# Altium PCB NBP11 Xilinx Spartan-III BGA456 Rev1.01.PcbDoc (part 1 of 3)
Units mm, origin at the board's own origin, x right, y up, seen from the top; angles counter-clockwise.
Board outline 69 x 80.99 mm, 6 copper layers (Top Layer, MidLayer1, InternalPlane1, InternalPlane2, MidLayer2, Bottom Layer); 105 components, 277 nets, 967 pads, 559 vias.
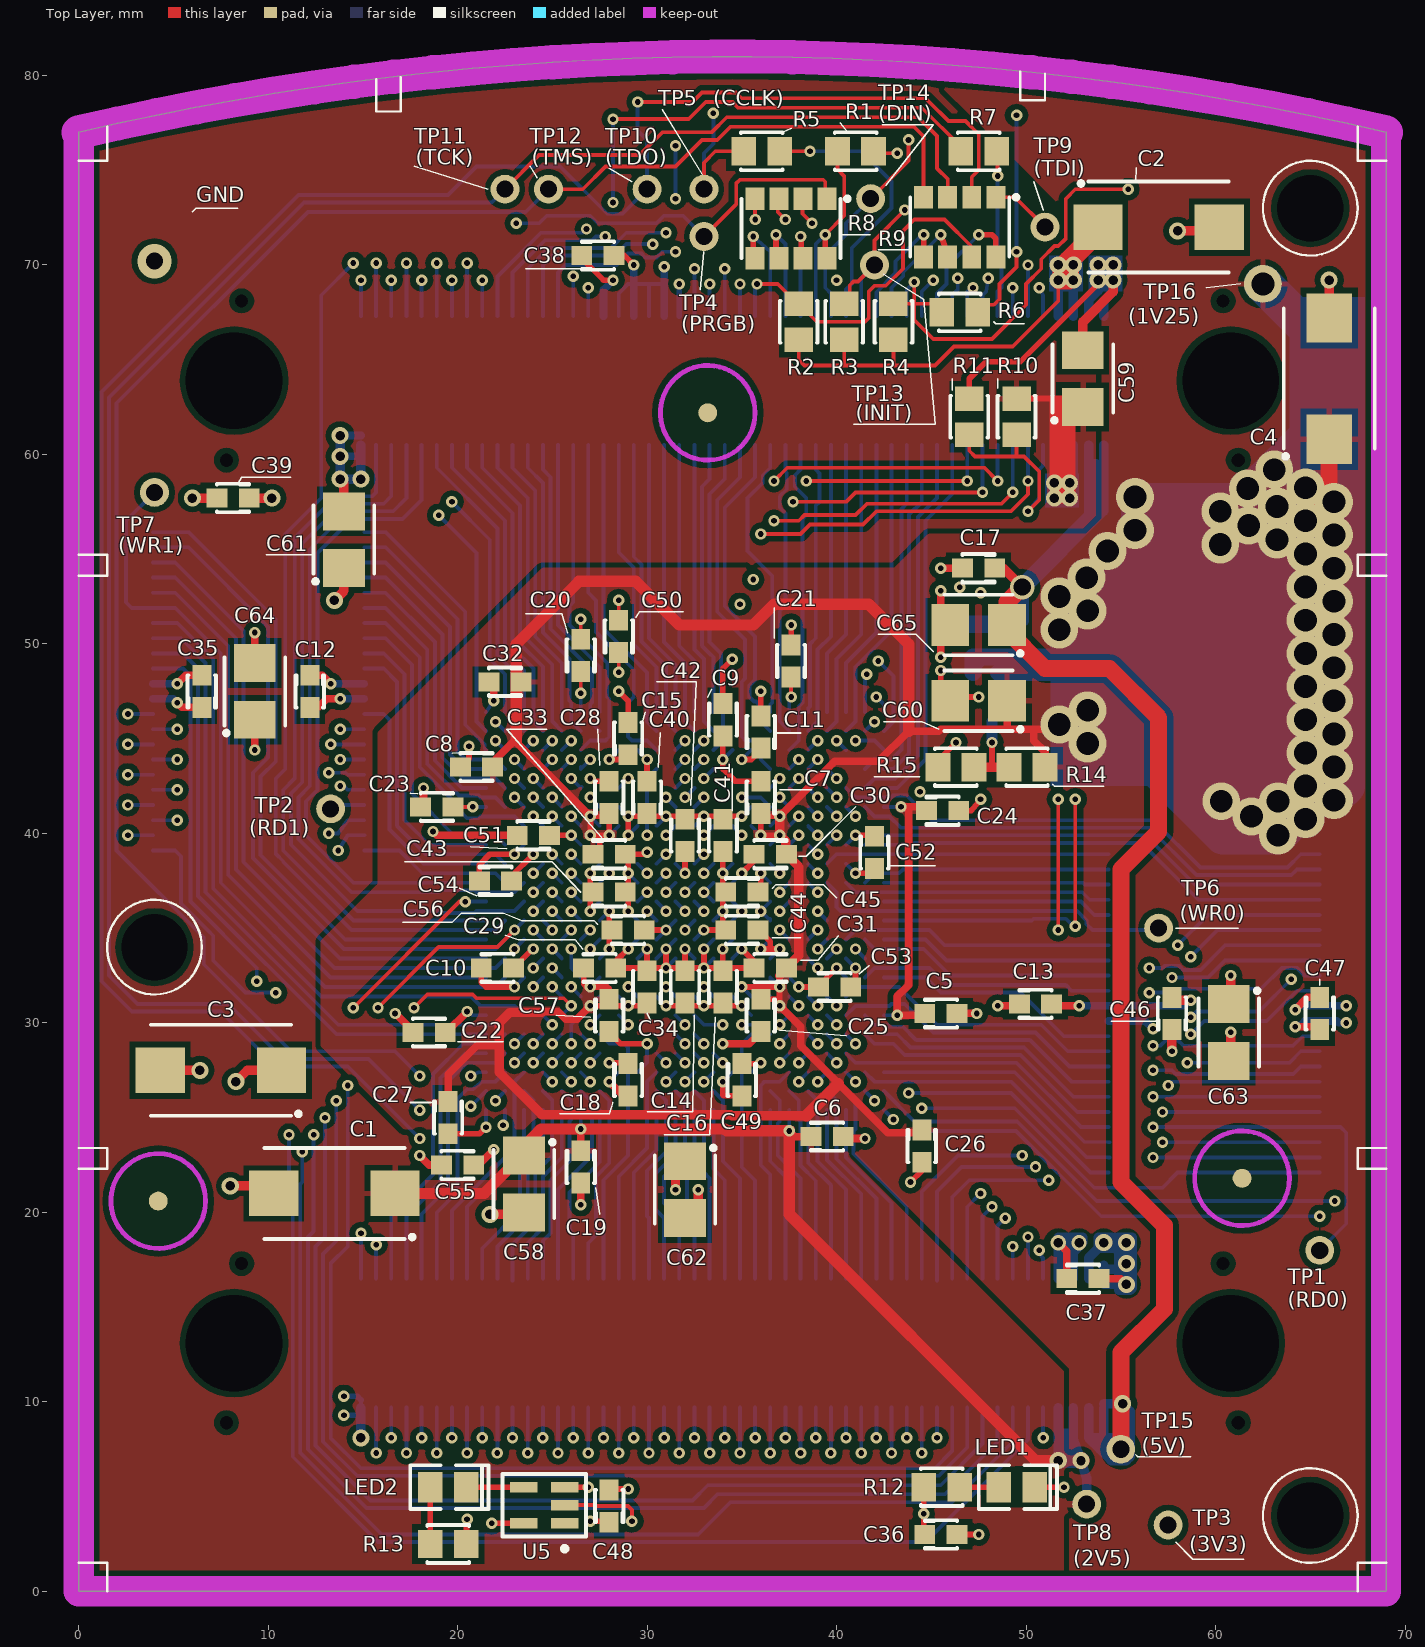
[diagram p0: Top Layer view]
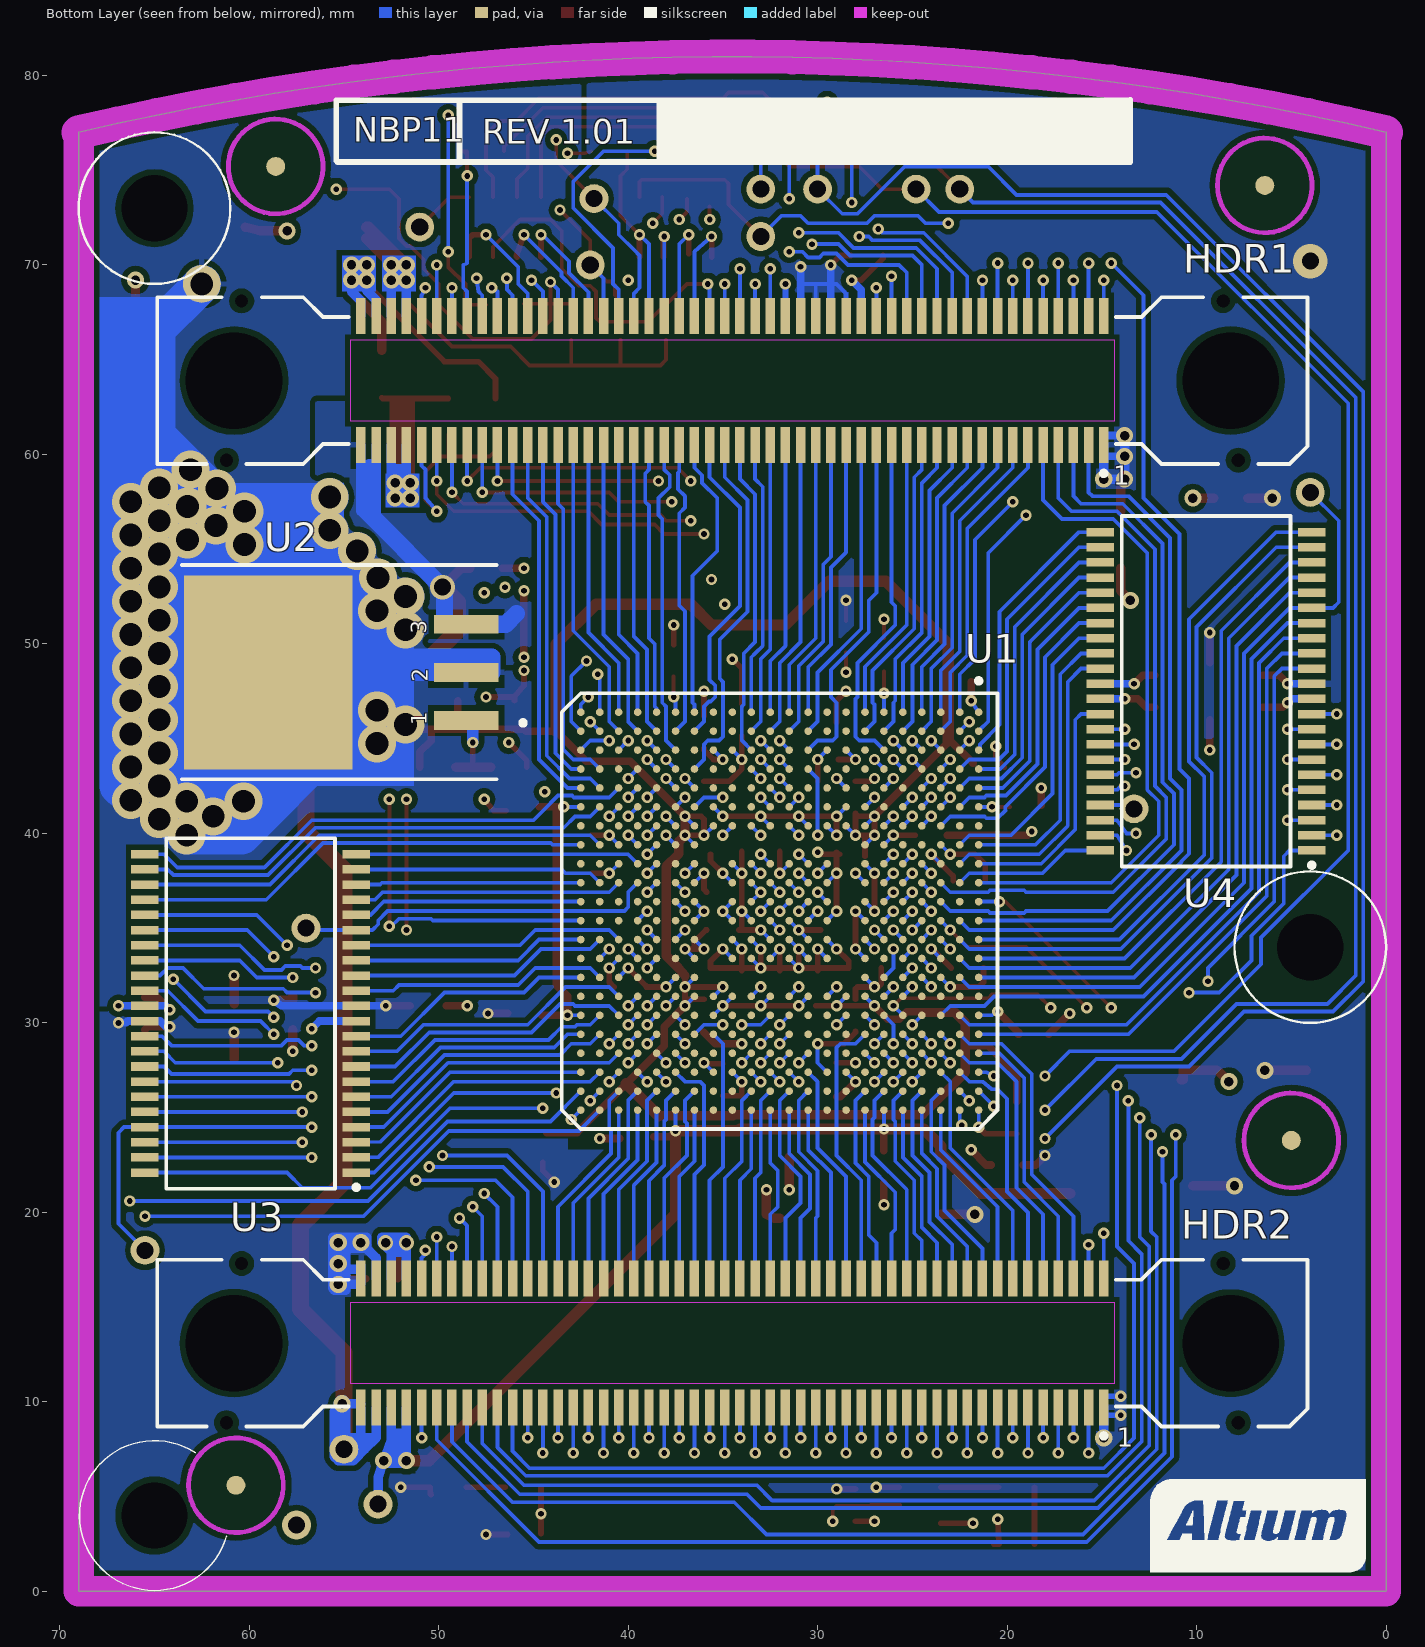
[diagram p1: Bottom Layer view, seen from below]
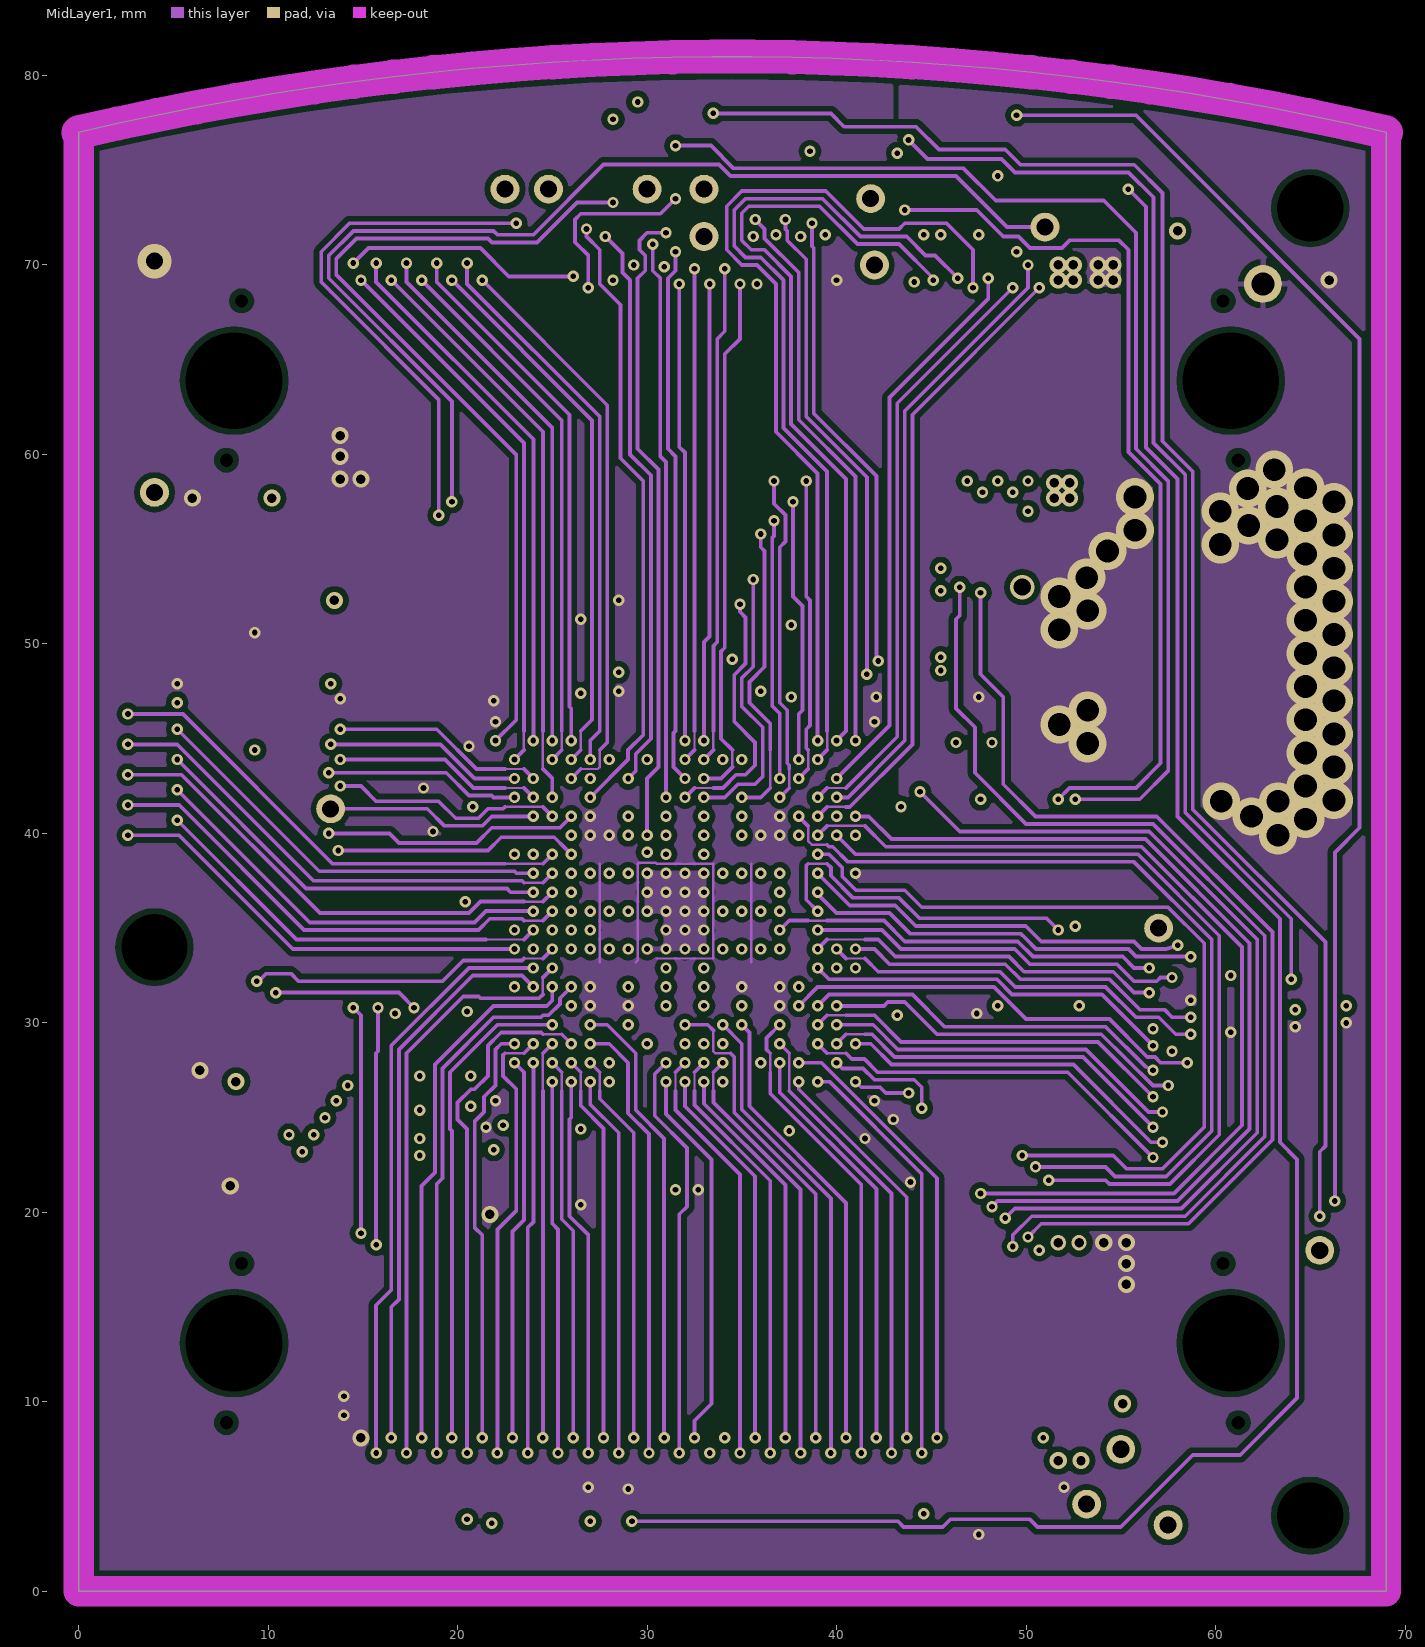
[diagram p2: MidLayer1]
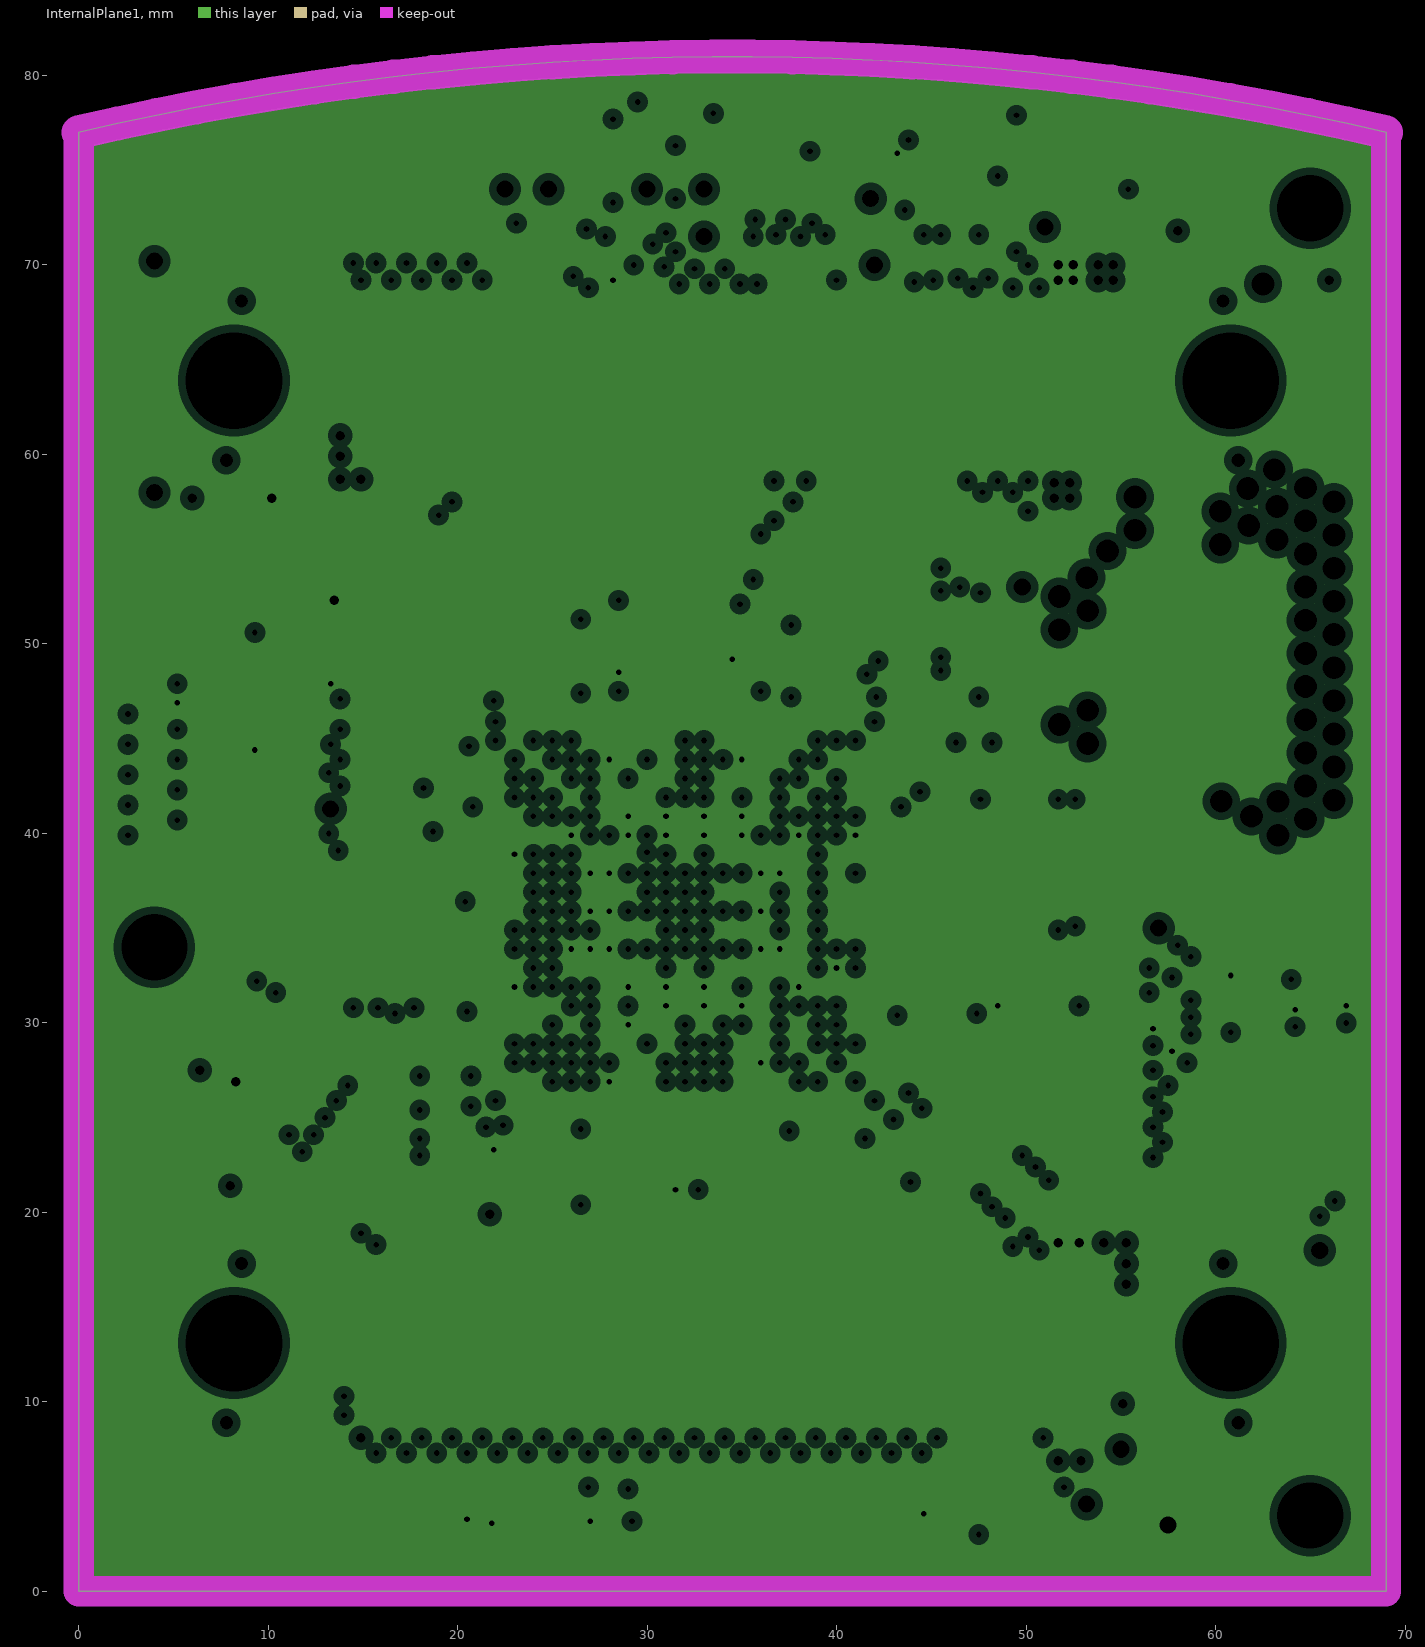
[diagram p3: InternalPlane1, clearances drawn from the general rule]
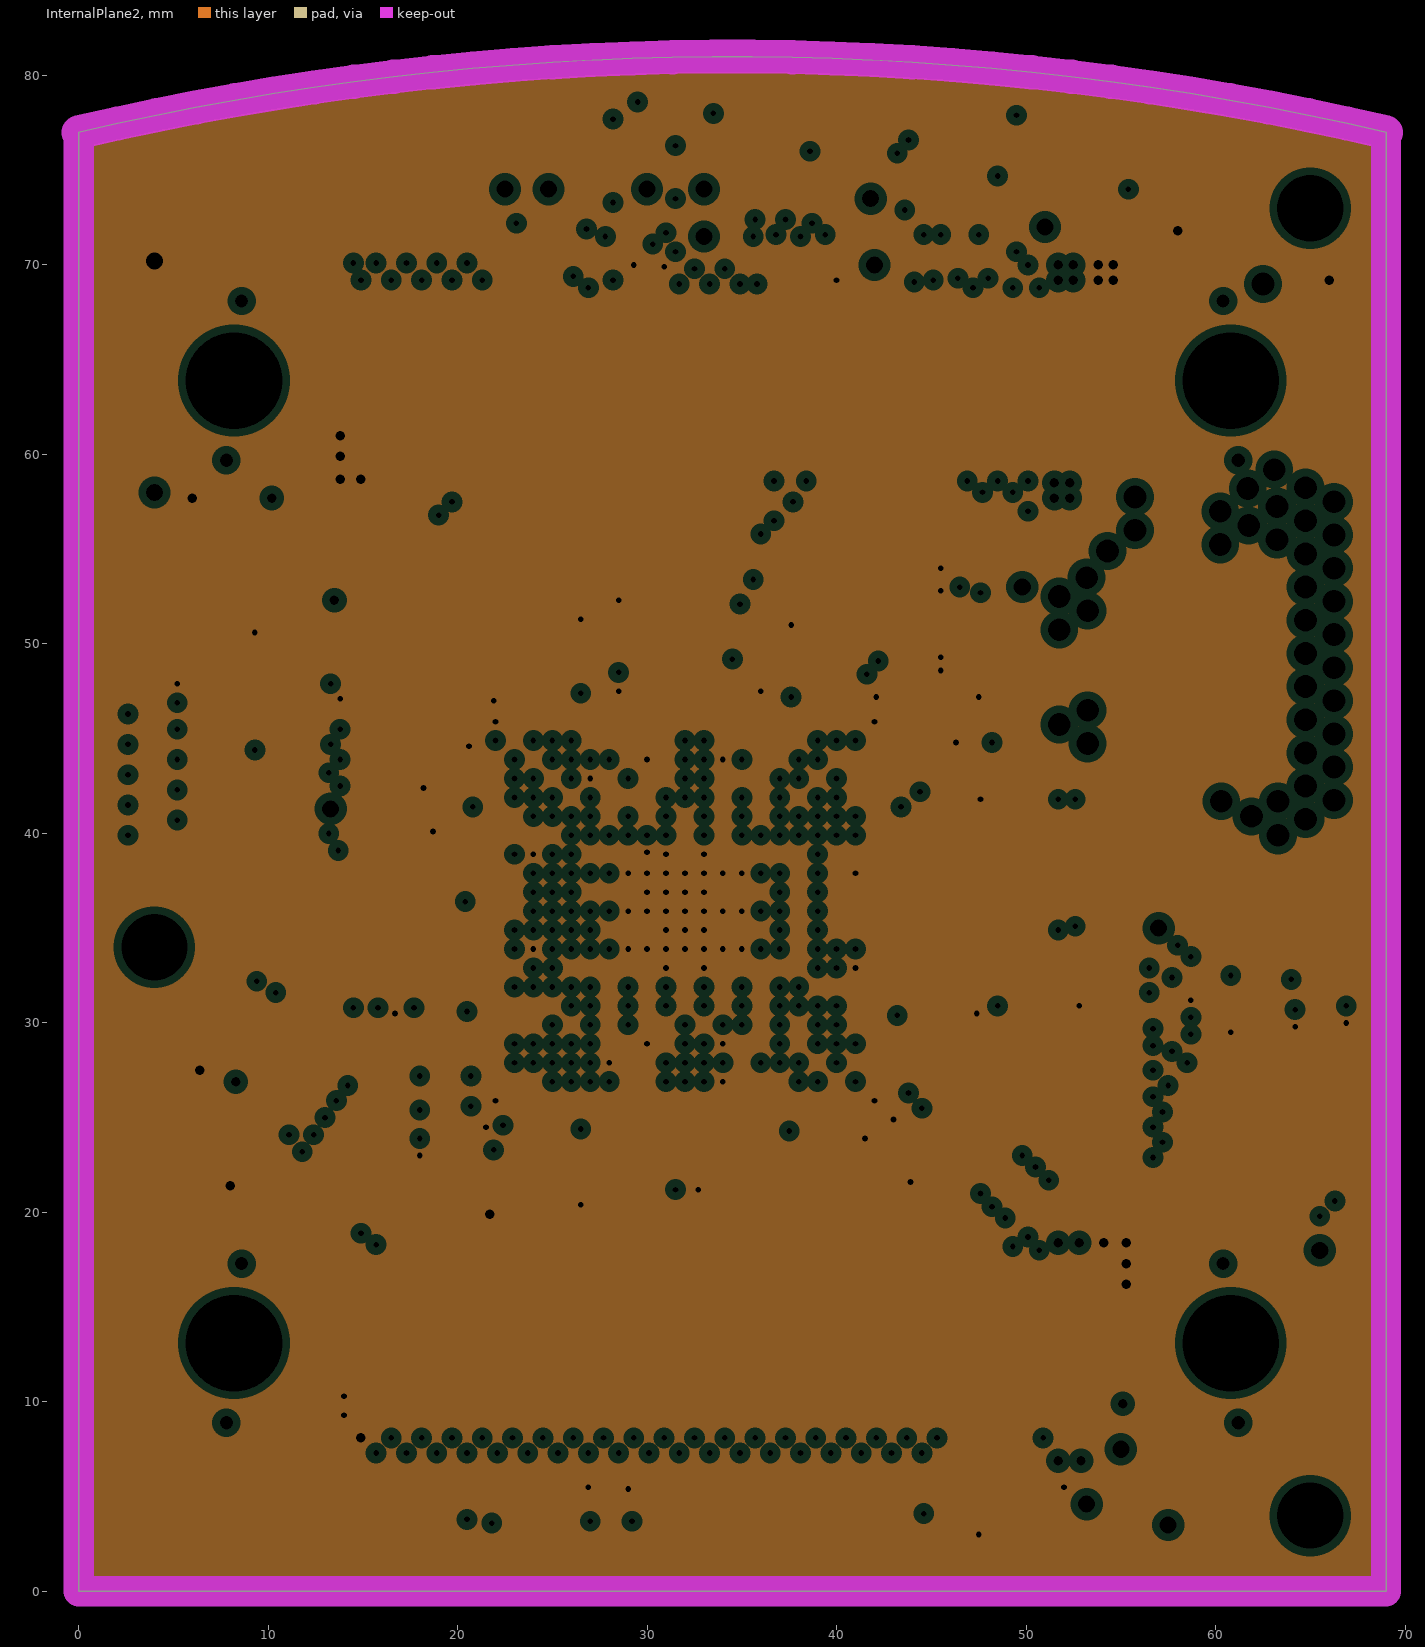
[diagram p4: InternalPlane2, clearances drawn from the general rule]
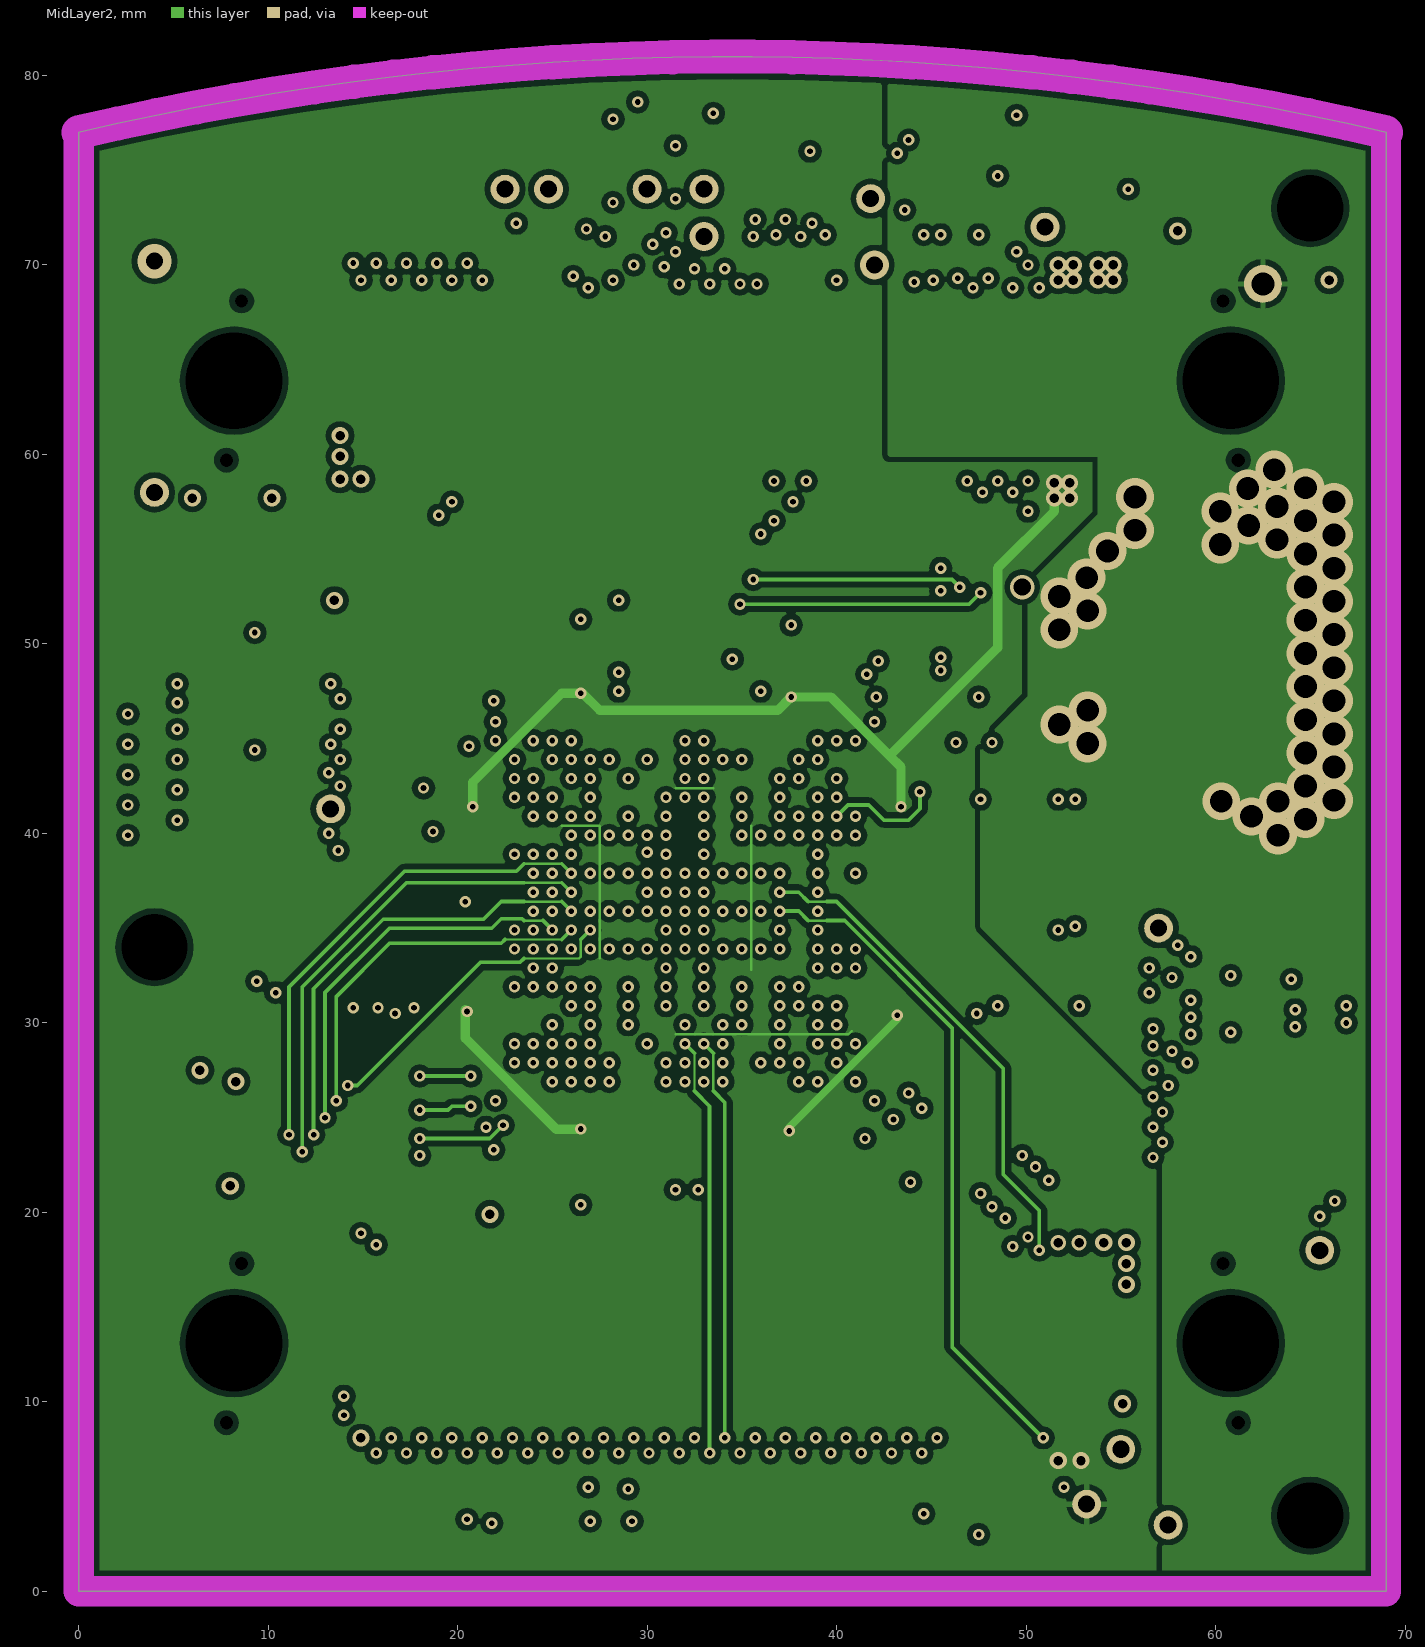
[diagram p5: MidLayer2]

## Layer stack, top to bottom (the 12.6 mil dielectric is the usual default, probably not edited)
Top Layer: signal copper 0.0356
Dielectric: core 0.32, FR-4, Dk 4.8
MidLayer1: signal copper 0.0356
Dielectric: prepreg 0.32, FR-4, Dk 4.8
InternalPlane1: plane copper 0.0356, net VCC
Dielectric: core 0.32, FR-4, Dk 4.8
InternalPlane2: plane copper 0.0356, net GND
Dielectric: prepreg 0.32, FR-4, Dk 4.8
MidLayer2: signal copper 0.0356
Dielectric: core 0.32, FR-4, Dk 4.8
Bottom Layer: signal copper 0.0356

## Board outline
0,0 0.001,77 cw(c34.5,-69.801) 69,77 69,0

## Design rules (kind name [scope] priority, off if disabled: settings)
Clearance Clearance_Polygons [InPolygon] p1: gap=0.3
Clearance "InnerLayer Track-Via Clearance" [OnMid And IsTrack vs IsVia] p2: gap=0.127
Clearance "Via-Via Clearance" [IsVia vs IsVia] p3: gap=0.3
Clearance "Pad-Pad Clearance Same Net" [IsPad vs IsPad] p4: gap=0.254
Clearance "Via-Pad Clearance" [IsVia vs IsPad] p5: gap=0.2
Clearance "General Clearance" [All] p6: gap=0.2
ComponentClearance [All] p1: gap=0.2 collisioncheckmode=3 verticalgap=0.254 showdistances=FALSE
FabricationTestPointUsage TestPointUsage [All] p1 off: valid=0 allowmultiple=FALSE
FabricationTestpoint Testpoint [All] p1 off: side=3 testpointundercomponent=TRUE minsize=1.016 maxsize=2.54 preferedsize=1.524 minholesize=0 maxholesize=1.016 preferedholesize=0.813 testpointgrid=0.025 allowsidetop=TRUE allowsidebottom=TRUE usegrid=TRUE gridtolerance=0
HoleSize [All] p1: absolutevalues=TRUE maxlimit=5.2 minlimit=0.25 maxpercent=80.000 minpercent=20.000
PlaneClearance [All] p1: clearance=0.4
PlaneConnect [All] p1: planeconnectstyle=Direct reliefexpansion=0.5 reliefentries=4 reliefconductorwidth=0.25 reliefairgap=0.25
PolygonConnect [All] p1: connectstyle=Relief reliefconductorwidth=0.3 reliefentries=4 polygonreliefangle="90 Angle"
RoutingVias [All] p1 off: holewidth=0.3 width=0.6 viastyle="Through Hole" minholewidth=0.3 minwidth=0.6 maxholewidth=0.5 maxwidth=0.9
SMDNeckDown [All] p1: percent=100.000
SilkscreenOverComponentPads [All] p1: minsilkscreentomaskgap=0.254
SolderMaskExpansion SolderMaskExpansion_Vias [IsVia] p1: expansion=-0.65
SolderMaskExpansion [All] p2: expansion=0.1
Width [All] p1: maxlimit=2.5 minlimit=0.127 preferedwidth=0.203 toplayer_minwidth=0.2 toplayer_prefwidth=0.2 midlayer1_prefwidth=0.2 bottomlayer_prefwidth=0.2
21 further rules are at their usual default settings.

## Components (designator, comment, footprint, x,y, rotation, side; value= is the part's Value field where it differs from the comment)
C1 "220uF/4V" MCCT-D 13.5,21 r180 top
C2 "220uF/4V" MCCT-D 57,72 r0 top
C3 "220uF/4V" MCCT-D 7.5,27.5 r180 top
C4 "220uF/4V" MCCT-D 66,64 r90 top
C5 "220nF" CC1608-0603 45.5,30.5 r0 top
C6 "220nF" CC1608-0603 39.5,24 r0 top
C7 "220nF" CC1608-0603 36,41.9 r90 top
C8 "220nF" CC1608-0603 21,43.5 r180 top
C9 "220nF" CC1608-0603 34,46 r270 top
C10 "220nF" CC1608-0603 22.1,32.9 r0 top
C11 "220nF" CC1608-0603 36,45.35 r90 top
C12 "220nF" CC1608-0603 12.2,47.5 r270 top
C13 "220nF" CC1608-0603 50.5,31 r0 top
C14 "220nF" CC1608-0603 32,31.9 r90 top
C15 "220nF" CC1608-0603 29,45 r90 top
C16 "220nF" CC1608-0603 34,31.9 r90 top
C17 "220nF" CC1608-0603 47.5,54 r180 top
C18 "220nF" CC1608-0603 29,27 r270 top
C19 "10nF" CC1608-0603 26.5,22.4 r270 top
C20 "10nF" CC1608-0603 26.5,49.4 r90 top
C21 "10nF" CC1608-0603 37.6,49.1 r90 top
C22 "10nF" CC1608-0603 18.5,29.5 r180 top
C23 "10nF" CC1608-0603 18.9,41.4 r180 top
C24 "10nF" CC1608-0603 45.6,41.2 r0 top
C25 "10nF" CC1608-0603 36,30.4 r270 top
C26 "10nF" CC1608-0603 44.5,23.5 r270 top
C27 "10nF" CC1608-0603 19.5,25 r270 top
C28 "10nF" CC1608-0603 28,41.9 r90 top
C29 "10nF" CC1608-0603 27.5,32.9 r0 top
C30 "10nF" CC1608-0603 36.5,38.9 r180 top
C31 "10nF" CC1608-0603 36.5,32.9 r180 top
C32 "10nF" CC1608-0603 22.5,48 r180 top
C33 "10nF" CC1608-0603 28,38.9 r0 top
C34 "10nF" CC1608-0603 30,31.9 r90 top
C35 "10nF" CC1608-0603 6.5,47.5 r90 top
C36 "10nF" CC1608-0603 45.5,3 r0 top
C37 "10nF" CC1608-0603 53,16.5 r0 top
C38 "10nF" CC1608-0603 27.4,70.498 r0 top
C39 "10nF" CC1608-0603 8.15,57.7 r180 top
C40 "10nF" CC1608-0603 30,41.9 r90 top
C41 "10nF" CC1608-0603 34,39.9 r270 top
C42 "10nF" CC1608-0603 32,39.9 r270 top
C43 "10nF" CC1608-0603 28,36.9 r0 top
C44 "10nF" CC1608-0603 35,34.9 r180 top
C45 "10nF" CC1608-0603 35,36.9 r180 top
C46 "10nF" CC1608-0603 57.7,30.5 r90 top
C47 "10nF" CC1608-0603 65.5,30.5 r270 top
C48 "10nF" CC1608-0603 28,4.5 r90 top
C49 "10nF" CC1608-0603 35,27 r270 top
C50 "10nF" CC1608-0603 28.5,50.4 r90 top
C51 "10nF" CC1608-0603 24,39.9 r180 top
C52 "10nF" CC1608-0603 42,39 r270 top
C53 "10nF" CC1608-0603 39.9,31.9 r0 top
C54 "10nF" CC1608-0603 22,37.5 r0 top
C55 "10nF" CC1608-0603 20,22.5 r180 top
C56 "10nF" CC1608-0603 29,34.9 r0 top
C57 "10nF" CC1608-0603 28,30.4 r270 top
C58 "10uF" MCCT-B 23.5,21.5 r270 top
C59 "10uF" MCCT-B 53,64 r90 top
C60 "10uF" MCCT-B 47.5,47 r180 top
C61 "10uF" MCCT-B 14,55.5 r90 top
C62 "10uF" MCCT-B 32,21.2 r270 top
C63 "10uF" MCCT-B 60.7,29.5 r270 top
C64 "10uF" MCCT-B 9.3,47.5 r90 top
C65 "10uF" MCCT-B 47.5,51 r180 top
HDR1 "54075-1009-HD1" 54075 34.5,63.9 r0 bottom locked
HDR2 "54075-1009-HD2" 54075 34.5,13.1 r0 bottom locked
LED1 "HSMH-C170" "SMD _LED" 49.5,5.5 r180 top locked
LED2 "HSMG-C170" "SMD _LED" 19.5,5.5 r180 top locked
R1 "4k7" CR2012-0805 41,76 r0 top
R2 "4k7" CR2012-0805 38,67 r270 top
R3 "4k7" CR2012-0805 40.4,67 r270 top
R4 "4K7" CR2012-0805 43,67 r90 top
R5 "100R" CR2012-0805 36.05,76 r180 top
R6 "100R" CR2012-0805 46.5,67.5 r0 top
R7 "100R" CR2012-0805 47.5,76 r0 top
R8 "100R" MNR34 37.595,71.925 r270 top
R9 "100R" MNR34 46.5,72 r270 top
R10 "82R/1%" CR2012-0805 49.5,62 r270 top
R11 "680R/1%" CR2012-0805 47,62 r90 top
R12 "270R" CR2012-0805 45.55,5.5 r0 top
R13 "270R" CR2012-0805 19.5,2.5 r0 top
R14 "Do Not Mount" CR2012-0805 50.05,43.5 r180 top
R15 "0R" CR2012-0805 46.3,43.5 r180 top
TP1 "(RD0)" TestPin#1 65.5,18 r0 top
TP2 "(RD1)" TestPin#1 13.3,41.3 r90 top
TP3 "(3V3)" TestPin#1 57.5,3.5 r90 top
TP4 "(PRGB)" TestPin#1 33,71.5 r90 top
TP5 "(CCLK)" TestPin#1 33,74 r90 top
TP6 "(WR0)" TestPin#1 57,35 r90 top
TP7 "(WR1)" TestPin#1 4,58 r90 top
TP8 "(2V5)" TestPin#1 53.2,4.6 r90 top
TP9 "(TDI)" TestPin#1 51,72 r90 top
TP10 "(TDO)" TestPin#1 30,74 r90 top
TP11 "(TCK)" TestPin#1 22.5,74 r90 top
TP12 "(TMS)" TestPin#1 24.8,74 r90 top
TP13 "(INIT)" TestPin#1 42,70 r90 top
TP14 "(DIN)" TestPin#1 41.8,73.5 r90 top
TP15 "(5V)" TestPin#1 55,7.5 r90 top
TP16 "(1V25)" TestPin#2 62.5,69 r90 top
U1 "XC3S400-5FG456C" FG456 32,35.9 r270 bottom
U2 "LM1084IS-ADJ" TO-263 48.55,45.96 r90 bottom
U3 "SRAM 512Kx16 TSOP44" SO-G44/P.8 59.925,30.5 r90 bottom
U4 "SRAM 512Kx16 TSOP44" SO-G44/P.8 9.5,47.5 r90 bottom
U5 "SN74LVC1G04DBV" SO-G5/P.95 24.575,4.55 r90 top

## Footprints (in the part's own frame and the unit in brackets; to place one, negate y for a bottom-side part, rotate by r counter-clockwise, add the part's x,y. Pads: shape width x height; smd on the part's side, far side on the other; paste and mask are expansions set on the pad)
54075 [mm] "Connector; Docking Station, Receptacle; 100 Position; Vertical"
  rect 0.5x1.9 smd: 1(-19.6,3.4) 2(-19.6,-3.4) 3(-18.8,3.4) 4(-18.8,-3.4) 5(-18,3.4) 6(-18,-3.4) 7(-17.2,3.4) 8(-17.2,-3.4) 9(-16.4,3.4) 10(-16.4,-3.4) 11(-15.6,3.4) 12(-15.6,-3.4) 13(-14.8,3.4) 14(-14.8,-3.4) 15(-14,3.4) 16(-14,-3.4) 17(-13.2,3.4) 18(-13.2,-3.4) 19(-12.4,3.4) 20(-12.4,-3.4) 21(-11.6,3.4) 22(-11.6,-3.4) 23(-10.8,3.4) 24(-10.8,-3.4) 25(-10,3.4) 26(-10,-3.4) 27(-9.2,3.4) 28(-9.2,-3.4) 29(-8.4,3.4) 30(-8.4,-3.4) 31(-7.6,3.4) 32(-7.6,-3.4) 33(-6.8,3.4) 34(-6.8,-3.4) 35(-6,3.4) 36(-6,-3.4) 37(-5.2,3.4) 38(-5.2,-3.4) 39(-4.4,3.4) 40(-4.4,-3.4) 41(-3.6,3.4) 42(-3.6,-3.4) 43(-2.8,3.4) 44(-2.8,-3.4) 45(-2,3.4) 46(-2,-3.4) 47(-1.2,3.4) 48(-1.2,-3.4) 49(-0.4,3.4) 50(-0.4,-3.4) 51(0.4,3.4) 52(0.4,-3.4) 53(1.2,3.4) 54(1.2,-3.4) 55(2,3.4) 56(2,-3.4) 57(2.8,3.4) 58(2.8,-3.4) 59(3.6,3.4) 60(3.6,-3.4) 61(4.4,3.4) 62(4.4,-3.4) 63(5.2,3.4) 64(5.2,-3.4) 65(6,3.4) 66(6,-3.4) 67(6.8,3.4) 68(6.8,-3.4) 69(7.6,3.4) 70(7.6,-3.4) 71(8.4,3.4) 72(8.4,-3.4) 73(9.2,3.4) 74(9.2,-3.4) 75(10,3.4) 76(10,-3.4) 77(10.8,3.4) 78(10.8,-3.4) 79(11.6,3.4) 80(11.6,-3.4) 81(12.4,3.4) 82(12.4,-3.4) 83(13.2,3.4) 84(13.2,-3.4) 85(14,3.4) 86(14,-3.4) 87(14.8,3.4) 88(14.8,-3.4) 89(15.6,3.4) 90(15.6,-3.4) 91(16.4,3.4) 92(16.4,-3.4) 93(17.2,3.4) 94(17.2,-3.4) 95(18,3.4) 96(18,-3.4) 97(18.8,3.4) 98(18.8,-3.4) 99(19.6,3.4) 100(19.6,-3.4)
  round 0.5 hole 0.7 unplated: MH1(-26.7,4.2) MH2(-25.9,-4.2) MH3(26.7,4.2) MH4(25.9,-4.2)
  round 4.8 hole 5.1 unplated: MH5(-26.3,0) MH6(26.3,0)
  Top Layer keep-out region: -20.15,2.15 20.15,2.15 20.15,-2.15 -20.15,-2.15
  silkscreen extent -30.35,-4.4 30.35,5.02
CC1608-0603 [mm]
  rect 1.1x1 smd: 1(-0.85,0) 2(0.85,0)
  silkscreen extent -0.85,-0.75 0.85,0.75
CR2012-0805 [mm]
  rect 1.3x1.5 smd: 1(-0.95,0) 2(0.95,0)
  silkscreen extent -1.1,-1 1.1,1
FG456 [mm] "456-Ball Fine Pitch Ball Grid Array (FG456)"
  round 0.4 smd: A1(-10.5,10.5) A2(-9.5,10.5) A3(-8.5,10.5) A4(-7.5,10.5) A5(-6.5,10.5) A6(-5.5,10.5) A7(-4.5,10.5) A8(-3.5,10.5) A9(-2.5,10.5) A10(-1.5,10.5) A11(-0.5,10.5) A12(0.5,10.5) A13(1.5,10.5) A14(2.5,10.5) A15(3.5,10.5) A16(4.5,10.5) A17(5.5,10.5) A18(6.5,10.5) A19(7.5,10.5) A20(8.5,10.5) A21(9.5,10.5) A22(10.5,10.5) AA1(-10.5,-9.5) AA2(-9.5,-9.5) AA3(-8.5,-9.5) AA4(-7.5,-9.5) AA5(-6.5,-9.5) AA6(-5.5,-9.5) AA7(-4.5,-9.5) AA8(-3.5,-9.5) AA9(-2.5,-9.5) AA10(-1.5,-9.5) AA11(-0.5,-9.5) AA12(0.5,-9.5) AA13(1.5,-9.5) AA14(2.5,-9.5) AA15(3.5,-9.5) AA16(4.5,-9.5) AA17(5.5,-9.5) AA18(6.5,-9.5) AA19(7.5,-9.5) AA20(8.5,-9.5) AA21(9.5,-9.5) AA22(10.5,-9.5) AB1(-10.5,-10.5) AB2(-9.5,-10.5) AB3(-8.5,-10.5) AB4(-7.5,-10.5) AB5(-6.5,-10.5) AB6(-5.5,-10.5) AB7(-4.5,-10.5) AB8(-3.5,-10.5) AB9(-2.5,-10.5) AB10(-1.5,-10.5) AB11(-0.5,-10.5) AB12(0.5,-10.5) AB13(1.5,-10.5) AB14(2.5,-10.5) AB15(3.5,-10.5) AB16(4.5,-10.5) AB17(5.5,-10.5) AB18(6.5,-10.5) AB19(7.5,-10.5) AB20(8.5,-10.5) AB21(9.5,-10.5) AB22(10.5,-10.5) B1(-10.5,9.5) B2(-9.5,9.5) B3(-8.5,9.5) B4(-7.5,9.5) B5(-6.5,9.5) B6(-5.5,9.5) B7(-4.5,9.5) B8(-3.5,9.5) B9(-2.5,9.5) B10(-1.5,9.5) B11(-0.5,9.5) B12(0.5,9.5) B13(1.5,9.5) B14(2.5,9.5) B15(3.5,9.5) B16(4.5,9.5) B17(5.5,9.5) B18(6.5,9.5) B19(7.5,9.5) B20(8.5,9.5) B21(9.5,9.5) B22(10.5,9.5) C1(-10.5,8.5) C2(-9.5,8.5) C3(-8.5,8.5) C4(-7.5,8.5) C5(-6.5,8.5) C6(-5.5,8.5) C7(-4.5,8.5) C8(-3.5,8.5) C9(-2.5,8.5) C10(-1.5,8.5) C11(-0.5,8.5) C12(0.5,8.5) C13(1.5,8.5) C14(2.5,8.5) C15(3.5,8.5) C16(4.5,8.5) C17(5.5,8.5) C18(6.5,8.5) C19(7.5,8.5) C20(8.5,8.5) C21(9.5,8.5) C22(10.5,8.5) D1(-10.5,7.5) D2(-9.5,7.5) D3(-8.5,7.5) D4(-7.5,7.5) D5(-6.5,7.5) D6(-5.5,7.5) D7(-4.5,7.5) D8(-3.5,7.5) D9(-2.5,7.5) D10(-1.5,7.5) D11(-0.5,7.5) D12(0.5,7.5) D13(1.5,7.5) D14(2.5,7.5) D15(3.5,7.5) D16(4.5,7.5) D17(5.5,7.5) D18(6.5,7.5) D19(7.5,7.5) D20(8.5,7.5) D21(9.5,7.5) D22(10.5,7.5) E1(-10.5,6.5) E2(-9.5,6.5) E3(-8.5,6.5) E4(-7.5,6.5) E5(-6.5,6.5) E6(-5.5,6.5) E7(-4.5,6.5) E8(-3.5,6.5) E9(-2.5,6.5) E10(-1.5,6.5) E11(-0.5,6.5) E12(0.5,6.5) E13(1.5,6.5) E14(2.5,6.5) E15(3.5,6.5) E16(4.5,6.5) E17(5.5,6.5) E18(6.5,6.5) E19(7.5,6.5) E20(8.5,6.5) E21(9.5,6.5) E22(10.5,6.5) F1(-10.5,5.5) F2(-9.5,5.5) F3(-8.5,5.5) F4(-7.5,5.5) F5(-6.5,5.5) F6(-5.5,5.5) F7(-4.5,5.5) F8(-3.5,5.5) F9(-2.5,5.5) F10(-1.5,5.5) F11(-0.5,5.5) F12(0.5,5.5) F13(1.5,5.5) F14(2.5,5.5) F15(3.5,5.5) F16(4.5,5.5) F17(5.5,5.5) F18(6.5,5.5) F19(7.5,5.5) F20(8.5,5.5) F21(9.5,5.5) F22(10.5,5.5) G1(-10.5,4.5) G2(-9.5,4.5) G3(-8.5,4.5) G4(-7.5,4.5) G5(-6.5,4.5) G6(-5.5,4.5) G7(-4.5,4.5) G8(-3.5,4.5) G9(-2.5,4.5) G10(-1.5,4.5) G11(-0.5,4.5) G12(0.5,4.5) G13(1.5,4.5) G14(2.5,4.5) G15(3.5,4.5) G16(4.5,4.5) G17(5.5,4.5) G18(6.5,4.5) G19(7.5,4.5) G20(8.5,4.5) G21(9.5,4.5) G22(10.5,4.5) H1(-10.5,3.5) H2(-9.5,3.5) H3(-8.5,3.5) H4(-7.5,3.5) H5(-6.5,3.5) H6(-5.5,3.5) H7(-4.5,3.5) H16(4.5,3.5) H17(5.5,3.5) H18(6.5,3.5) H19(7.5,3.5) H20(8.5,3.5) H21(9.5,3.5) H22(10.5,3.5) J1(-10.5,2.5) J2(-9.5,2.5) J3(-8.5,2.5) J4(-7.5,2.5) J5(-6.5,2.5) J6(-5.5,2.5) J7(-4.5,2.5) J9(-2.5,2.5) J10(-1.5,2.5) J11(-0.5,2.5) J12(0.5,2.5) J13(1.5,2.5) J14(2.5,2.5) J16(4.5,2.5) J17(5.5,2.5) J18(6.5,2.5) J19(7.5,2.5) J20(8.5,2.5) J21(9.5,2.5) J22(10.5,2.5) K1(-10.5,1.5) K2(-9.5,1.5) K3(-8.5,1.5) K4(-7.5,1.5) K5(-6.5,1.5) K6(-5.5,1.5) K7(-4.5,1.5) K9(-2.5,1.5) K10(-1.5,1.5) K11(-0.5,1.5) K12(0.5,1.5) K13(1.5,1.5) K14(2.5,1.5) K16(4.5,1.5) K17(5.5,1.5) K18(6.5,1.5) K19(7.5,1.5) K20(8.5,1.5) K21(9.5,1.5) K22(10.5,1.5) L1(-10.5,0.5) L2(-9.5,0.5) L3(-8.5,0.5) L4(-7.5,0.5) L5(-6.5,0.5) L6(-5.5,0.5) L7(-4.5,0.5) L9(-2.5,0.5) L10(-1.5,0.5) L11(-0.5,0.5) L12(0.5,0.5) L13(1.5,0.5) L14(2.5,0.5) L16(4.5,0.5) L17(5.5,0.5) L18(6.5,0.5) L19(7.5,0.5) L20(8.5,0.5) L21(9.5,0.5) L22(10.5,0.5) M1(-10.5,-0.5) M2(-9.5,-0.5) M3(-8.5,-0.5) M4(-7.5,-0.5) M5(-6.5,-0.5) M6(-5.5,-0.5) M7(-4.5,-0.5) M9(-2.5,-0.5) M10(-1.5,-0.5) M11(-0.5,-0.5) M12(0.5,-0.5) M13(1.5,-0.5) M14(2.5,-0.5) M16(4.5,-0.5) M17(5.5,-0.5) M18(6.5,-0.5) M19(7.5,-0.5) M20(8.5,-0.5) M21(9.5,-0.5) M22(10.5,-0.5) N1(-10.5,-1.5) N2(-9.5,-1.5) N3(-8.5,-1.5) N4(-7.5,-1.5) N5(-6.5,-1.5) N6(-5.5,-1.5) N7(-4.5,-1.5) N9(-2.5,-1.5) N10(-1.5,-1.5) N11(-0.5,-1.5) N12(0.5,-1.5) N13(1.5,-1.5) N14(2.5,-1.5) N16(4.5,-1.5) N17(5.5,-1.5) N18(6.5,-1.5) N19(7.5,-1.5) N20(8.5,-1.5) N21(9.5,-1.5) N22(10.5,-1.5) P1(-10.5,-2.5) P2(-9.5,-2.5) P3(-8.5,-2.5) P4(-7.5,-2.5) P5(-6.5,-2.5) P6(-5.5,-2.5) P7(-4.5,-2.5) P9(-2.5,-2.5) P10(-1.5,-2.5) P11(-0.5,-2.5) P12(0.5,-2.5) P13(1.5,-2.5) P14(2.5,-2.5) P16(4.5,-2.5) P17(5.5,-2.5) P18(6.5,-2.5) P19(7.5,-2.5) P20(8.5,-2.5) P21(9.5,-2.5) P22(10.5,-2.5) R1(-10.5,-3.5) R2(-9.5,-3.5) R3(-8.5,-3.5) R4(-7.5,-3.5) R5(-6.5,-3.5) R6(-5.5,-3.5) R7(-4.5,-3.5) R16(4.5,-3.5) R17(5.5,-3.5) R18(6.5,-3.5) R19(7.5,-3.5) R20(8.5,-3.5) R21(9.5,-3.5) R22(10.5,-3.5) T1(-10.5,-4.5) T2(-9.5,-4.5) T3(-8.5,-4.5) T4(-7.5,-4.5) T5(-6.5,-4.5) T6(-5.5,-4.5) T7(-4.5,-4.5) T8(-3.5,-4.5) T9(-2.5,-4.5) T10(-1.5,-4.5) T11(-0.5,-4.5) T12(0.5,-4.5) T13(1.5,-4.5) T14(2.5,-4.5) T15(3.5,-4.5) T16(4.5,-4.5) T17(5.5,-4.5) T18(6.5,-4.5) T19(7.5,-4.5) T20(8.5,-4.5) T21(9.5,-4.5) T22(10.5,-4.5) U1(-10.5,-5.5) U2(-9.5,-5.5) U3(-8.5,-5.5) U4(-7.5,-5.5) U5(-6.5,-5.5) U6(-5.5,-5.5) U7(-4.5,-5.5) U8(-3.5,-5.5) U9(-2.5,-5.5) U10(-1.5,-5.5) U11(-0.5,-5.5) U12(0.5,-5.5) U13(1.5,-5.5) U14(2.5,-5.5) U15(3.5,-5.5) U16(4.5,-5.5) U17(5.5,-5.5) U18(6.5,-5.5) U19(7.5,-5.5) U20(8.5,-5.5) U21(9.5,-5.5) U22(10.5,-5.5) V1(-10.5,-6.5) V2(-9.5,-6.5) V3(-8.5,-6.5) V4(-7.5,-6.5) V5(-6.5,-6.5) V6(-5.5,-6.5) V7(-4.5,-6.5) V8(-3.5,-6.5) V9(-2.5,-6.5) V10(-1.5,-6.5) V11(-0.5,-6.5) V12(0.5,-6.5) V13(1.5,-6.5) V14(2.5,-6.5) V15(3.5,-6.5) V16(4.5,-6.5) V17(5.5,-6.5) V18(6.5,-6.5) V19(7.5,-6.5) V20(8.5,-6.5) V21(9.5,-6.5) V22(10.5,-6.5) W1(-10.5,-7.5) W2(-9.5,-7.5) W3(-8.5,-7.5) W4(-7.5,-7.5) W5(-6.5,-7.5) W6(-5.5,-7.5) W7(-4.5,-7.5) W8(-3.5,-7.5) W9(-2.5,-7.5) W10(-1.5,-7.5) W11(-0.5,-7.5) W12(0.5,-7.5) W13(1.5,-7.5) W14(2.5,-7.5) W15(3.5,-7.5) W16(4.5,-7.5) W17(5.5,-7.5) W18(6.5,-7.5) W19(7.5,-7.5) W20(8.5,-7.5) W21(9.5,-7.5) W22(10.5,-7.5) Y1(-10.5,-8.5) Y2(-9.5,-8.5) Y3(-8.5,-8.5) Y4(-7.5,-8.5) Y5(-6.5,-8.5) Y6(-5.5,-8.5) Y7(-4.5,-8.5) Y8(-3.5,-8.5) Y9(-2.5,-8.5) Y10(-1.5,-8.5) Y11(-0.5,-8.5) Y12(0.5,-8.5) Y13(1.5,-8.5) Y14(2.5,-8.5) Y15(3.5,-8.5) Y16(4.5,-8.5) Y17(5.5,-8.5) Y18(6.5,-8.5) Y19(7.5,-8.5) Y20(8.5,-8.5) Y21(9.5,-8.5) Y22(10.5,-8.5)
  silkscreen extent -12.27,-11.5 11.5,11.5
MCCT-B [mm]
  rect 2x2.2 smd: 1(-1.5,0) 2(1.5,0)
  silkscreen extent -2.3,-1.6 1.8,1.6
MCCT-D [mm]
  rect 2.6x2.4 smd: 1(-3.2,0) 2(3.2,0)
  silkscreen extent -4.2,-2.4 3.7,2.4
MNR34 [mm]
  rect 1.2x1 smd: 1(-1.575,1.905) 2(-1.575,0.635) 3(-1.575,-0.635) 4(-1.575,-1.905) 5(1.575,-1.905) 6(1.575,-0.635) 7(1.575,0.635) 8(1.575,1.905)
  silkscreen extent -1.67,-2.62 1.55,3.07
"SMD _LED" [mm]
  rect 1.3x1.6 smd: 1(0.95,0) 2(-0.95,0)
  silkscreen extent -2.13,-1.15 2,1.15
SO-G5/P.95 [mm]
  rect 0.55x1.45 smd: 1(-0.95,-1.075) 2(0,-1.075) 3(0.95,-1.075) 4(0.95,1.075) 5(-0.95,1.075)
  silkscreen extent -2.42,-2.2 1.65,2.2
SO-G44/P.8 [mm]
  rect 0.45x1.45 smd: 1(-8.4,-5.575) 2(-7.6,-5.575) 3(-6.8,-5.575) 4(-6,-5.575) 5(-5.2,-5.575) 6(-4.4,-5.575) 7(-3.6,-5.575) 8(-2.8,-5.575) 9(-2,-5.575) 10(-1.2,-5.575) 11(-0.4,-5.575) 12(0.4,-5.575) 13(1.2,-5.575) 14(2,-5.575) 15(2.8,-5.575) 16(3.6,-5.575) 17(4.4,-5.575) 18(5.2,-5.575) 19(6,-5.575) 20(6.8,-5.575) 21(7.6,-5.575) 22(8.4,-5.575) 23(8.4,5.575) 24(7.6,5.575) 25(6.8,5.575) 26(6,5.575) 27(5.2,5.575) 28(4.4,5.575) 29(3.6,5.575) 30(2.8,5.575) 31(2,5.575) 32(1.2,5.575) 33(0.4,5.575) 34(-0.4,5.575) 35(-1.2,5.575) 36(-2,5.575) 37(-2.8,5.575) 38(-3.6,5.575) 39(-4.4,5.575) 40(-5.2,5.575) 41(-6,5.575) 42(-6.8,5.575) 43(-7.6,5.575) 44(-8.4,5.575)
  silkscreen extent -9.3,-5.7 9.25,4.45
TestPin#1 [mil] "SingleTest Pin"
  round 60 hole 35.43: 1(0,0)
TestPin#2 [mil] "SingleTest Pin"
  round 78.74 hole 47.24: 1(0,0)
TO-263 [mm]
  rect 1x3.4 smd: 1(0,0) 2(2.54,0) 3(5.08,0)
  rect 10.25x8.9 smd: 4(2.54,10.45)
  silkscreen extent -3.1,-3.12 8.2,15

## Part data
C1 C2 C3 C4 C58 C59 C60 C61 C62 C63 C64 C65: library part CAP_POLAR, "Polar Capacitor"
C5 C6 C7 C8 C9 C10 C11 C12 C13 C14 C15 C16 C17 C18 C19 C20 C21 C22 C23 C24 C25 C26 C27 C28 C29 C30 C31 C32 C33 C34 C35 C36 C37 C38 C39 C40 C41 C42 C43 C44 C45 C46 C47 C48 C49 C50 C51 C52 C53 C54 C55 C56 C57: library part CAP, "Capacitor"
HDR1 HDR2: "Board-to-Board, Docking Station, 0.80mm (.031\") Pitch, Shielded Receptacle, Vertical, Ultra Low Profile, SMT"
LED1 LED2: library part HSMX-C670, "Typical RED GaAs SMD LED Agilent make"
R1 R2 R3 R4 R5 R6 R7 R10 R11 R12 R13 R14 R15: library part RES, "Resistor"
R8 R9: library part MNR34, "3216x4 Resistor Array"
TP1 TP2 TP3 TP4 TP5 TP6 TP7 TP8 TP9 TP10 TP11 TP12 TP13 TP14 TP15 TP16: library part TestPin
U1: "Spartan-3 1.2V FPGA, 264 User I/Os, 456-ball FBGA, High Performance, Commercial Grade"
U2: "5A Low Dropout Possitive Regulators"
U3 U4: "512Kx16Bit SRAM TSOP44"
U5: library part SN74AHC1G04DBVR

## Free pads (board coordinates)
  round 1 smd mask+2: FID(4.2,20.6) FID(33.2,62.2) FID(61.4,21.8)
  round 1 smd far side mask+2: FID(5,23.8) FID(6.4,74.2) FID(58.6,75.2) FID(60.7,5.6)
  round 3.2 hole 3.5 unplated: LP(4,34) LP(65,4) LP(65,73)

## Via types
v1: diameter 0.6, hole 0.3, Top Layer to Bottom Layer, tented both sides, 480 vias
v2: diameter 2, hole 1.2, Top Layer to Bottom Layer, tented both sides, 42 vias
v3: diameter 0.9, hole 0.5, Top Layer to Bottom Layer, tented both sides, 33 vias
v4: diameter 0.8, hole 0.5, Top Layer to Bottom Layer, tented both sides, 2 vias
v5: diameter 1.3, hole 0.9, Top Layer to Bottom Layer, tented both sides, 1 vias
v6: diameter 1.8, hole 0.9, Top Layer to Bottom Layer, tented both sides, 1 vias

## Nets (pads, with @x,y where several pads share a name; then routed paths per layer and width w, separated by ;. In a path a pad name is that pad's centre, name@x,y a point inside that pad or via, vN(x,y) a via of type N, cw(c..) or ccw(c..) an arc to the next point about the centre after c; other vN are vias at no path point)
+5: C17.1 C65.1 HDR1.97 HDR1.99 HDR2.97 HDR2.99 TP15.1 U2.3 | length 99.5
  Top Layer w0.5: C17.1@48.35,54 48.8,54 v5(49.8,53)
  Top Layer w0.9: C65.1@48.9,50.8 51,48.7 54.4,48.7 57,46.1 57,40.1 55,38.1 55,21.6 57.3,19.3 57.3,14.9 55,12.6 55,9.9 TP15.1@55,7.5 ; C65.1@49,51 49,52.2 v5(49.8,53)
  Bottom Layer w0.5: U2.3@49.5,51.5 49.5,53 49.65,53.15 53.3,56.8 ; U2.3@49.9,51.2 49.9,52.8 49.95,52.85 54.1,57 HDR1.99@54.1,60.5 ; 53.149,56.649 53.3,56.8 ; HDR2.97@53.3,9.7 53.3,8.1 ; HDR1.97@53.3,60.5 53.3,59.5 ; HDR2.99@54.1,9.7 54.1,8.1 ; HDR2.99@54.1,9.9 v3(55.1,9.9) 55.5,9.5 55.5,7.5 55.5,7.1 55.45,7.05 55.3,6.9 55,6.9 54.5,6.9 54.45,6.95 53.9,7.5 ; TP15.1@55,7.5 54.1,7.5 ; 55.1,8.3 54.9,8.1 54.1,8.1 ; 53.3,8.1 54.1,8.1 ; 53.3,8.1 53.9,7.5 ; 53.3,56.8 53.3,59.5 ; 53.3,56.8 53.7,57.2 53.7,59.5 53.3,59.5 ; 53.9,7.5 54.1,7.5 ; 54.1,7.5 54.1,8.1
  Bottom Layer w0.9: 45.9,51.6 46.46,51.04 U2.3@48.55,51.04 ; TP15.1@55,7.5 55.1,7.6 55.1,8.3 v3(55.1,9.9)
AUDIO_SPI_CSN: HDR1.11 U1.C2 | length 17
  Bottom Layer w0.2: HDR1.11@18.9,60.5 18.9,59.3 22.1,56.1 22.1,49.4 23,48.5 23,45.9 U1.C2@23.5,45.4
BLUE0: HDR1.14 U1.E4 | length 31.4
  MidLayer1 w0.127: 26.5,44.4 26.5,45.4
  MidLayer1 w0.2: v1(19.7,69.2) 27.1,61.8 27.1,46 26.5,45.4 ; v1(26,43.9) 26.5,44.4
  Bottom Layer w0.2: HDR1.14@19.7,67.3 v1(19.7,69.2) ; U1.E4@25.5,43.4 v1(26,43.9)
BLUE1: HDR1.16 U1.F4 | length 33
  MidLayer1 w0.2: v1(20.5,70.1) 20.5,69 27.5,62 27.5,45.4 27,44.9 v1(27,43.9)
  Bottom Layer w0.2: HDR1.16@20.5,67.3 v1(20.5,70.1) ; U1.F4@26.5,43.5 26.55,43.45 U1.F4@26.5,43.4 v1(27,43.9)
BOC_CTS: HDR1.13 U1.C1 | length 15.7
  Bottom Layer w0.2: HDR1.13@19.7,60.5 19.7,59.3 22.5,56.5 22.5,49.6 23.5,48.6 U1.C1@23.5,46.4
BOC_RTS: HDR1.17 U1.D1 | length 15.4
  Bottom Layer w0.2: HDR1.17@21.3,60.5 21.3,59.3 23.3,57.3 23.3,50 24.5,48.8 U1.D1@24.5,46.4
BOC_RX: HDR1.19 U1.E2 | length 16.5
  Bottom Layer w0.2: HDR1.19@22.1,60.5 22.1,59.3 23.7,57.7 23.7,50.2 25,48.9 25,45.9 U1.E2@25.5,45.4
BOC_TX: HDR1.15 U1.D2 | length 16.8
  Bottom Layer w0.2: HDR1.15@20.5,60.5 20.5,59.3 22.9,56.9 22.9,49.8 24,48.7 24,45.9 U1.D2@24.5,45.4
BUZZER: HDR2.24 U1.E22 | length 9.6
  Bottom Layer w0.2: HDR2.24@23.7,16.5 23.7,18.4 24.5,19.2 24.5,21.9 25.5,22.9 U1.E22@25.5,25.4
CAN_RXD: HDR1.4 U1.C3 | length 32.1
  MidLayer1 w0.2: v1(15.7,70.1) 15.7,69.1 24,60.8 v1(24,44.9)
  Bottom Layer w0.2: HDR1.4@15.7,67.3 v1(15.7,70.1) ; U1.C3@23.5,44.4 v1(24,44.9)
CAN_TXD: HDR1.2 U1.C4 | length 31.7
  MidLayer1 w0.127: 23.5,44.4 23.5,45.4
  MidLayer1 w0.2: v1(14.9,69.2) 23.5,60.6 23.5,45.4 ; v1(23,43.9) 23.5,44.4
  Bottom Layer w0.2: HDR1.2@14.9,67.3 v1(14.9,69.2) ; v1(23,43.9) U1.C4@23.5,43.4
FPGA_AUX0: R7.1 U1.B3 | length 70.9
  Top Layer w0.2: v1(28.2,77.698) 32.198,77.698 33.1,78.6 34.5,78.6 34.8,78.3 44.5,78.3 46.55,76.25 R7.1@46.55,76
  MidLayer1 w0.2: v1(22,44.9) 23.1,46 23.1,59.966 13.6,69.466 13.6,70.334 14.666,71.4 21.6,71.4 21.808,71.192 24.192,71.192 26.3,73.3 v1(28.2,73.3)
  Bottom Layer w0.2: v1(22,44.9) U1.B3@22.5,44.4 ; v1(28.2,73.3) v1(28.2,77.698)
FPGA_AUX0_R: HDR1.86 R7.2 | length 9.2
  Top Layer w0.2: v1(48.5,74.7) 48.5,76 48.7,76 R7.2@48.6,75.9
  Bottom Layer w0.2: HDR1.86@48.5,67.3 48.5,68.6 48.7,68.8 48.7,70 48.5,70.1 v1(48.5,74.7)
FPGA_AUX1: HDR1.88 U1.V5 | length 34
  MidLayer1 w0.127: 39.5,42.4 40.5,42.4
  MidLayer1 w0.2: v1(39,41.9) 39.5,42.4 ; 40.5,42.4 43.2,45.1 43.2,62.7 v1(49.3,68.8)
  Bottom Layer w0.2: U1.V5@38.5,42.4 v1(39,41.9) ; HDR1.88@49.3,67.3 v1(49.3,68.8)
FPGA_AUX2: HDR1.90 U1.W5 | length 36
  MidLayer1 w0.2: v1(40,41.9) 40.6,41.9 43.6,44.9 43.6,62.3 50.1,68.8 v1(50.1,70)
  Bottom Layer w0.2: U1.W5@39.5,42.4 v1(40,41.9) ; HDR1.90@50.1,67.3 50.1,68.8 v1(50.1,70)
FPGA_AUX3: HDR1.92 U1.V6 | length 35.7
  MidLayer1 w0.127: 39.5,41.4 40.5,41.4
  MidLayer1 w0.2: v1(39,40.9) 39.5,41.4 ; 40.5,41.4 40.7,41.4 44,44.7 44,62.1 v1(50.7,68.8)
  Bottom Layer w0.2: U1.V6@38.5,41.4 v1(39,40.9) ; v1(50.7,68.8) 50.9,68.4 HDR1.92@50.9,67.3
FPGA_CCLK: R5.2 TP5.1 U1.AA22 | length 117.4
  Top Layer w0.2: TP5.1@33,74 33,75.4 33.6,76 R5.2@35.1,76
  MidLayer1 w0.2: v1(33.5,78) 39.7,78 40.4,77.3 44.2,77.3 45.4,76.1 48.9,76.1 49.713,75.287 55.713,75.287 57.2,73.8 57.2,60.7 58.8,59.1 58.8,41.266 65.8,34.266 65.8,23.5 65.5,23.2 v1(65.5,19.8)
  Bottom Layer w0.2: TP5.1@33,74 33,75.9 33.5,76.4 v1(33.5,78) ; U1.AA22@41.5,25.4 42.6,24.3 49.469,24.3 53.969,19.8 v1(65.5,19.8)
FPGA_CCLK_R: HDR1.66 R5.1 | length 14.7
  Top Layer w0.2: R5.1@37,76 v1(38.6,76)
  Bottom Layer w0.2: v1(38.6,76) 41.294,76 41.297,76.003 42.9,74.4 42.9,73 40.8,70.9 40.8,69 40.5,68.7 HDR1.66@40.5,67.3
FPGA_CLK: HDR2.2 U1.A11 | length 23.8
  Top Layer w0.2: v1(14.5,30.8) 20.1,36.4 v1(20.4,36.4)
  MidLayer1 w0.2: v1(14.5,30.8) 14.9,30.4 v1(14.9,18.9)
  Bottom Layer w0.2: HDR2.2@14.9,16.5 v1(14.9,18.9) ; v1(20.4,36.4) U1.A11@21.5,36.4
FPGA_CLK_1: HDR1.30 U1.B12 | length 61.5
  MidLayer1 w0.2: v1(14.5,70.1) 15.3,70.9 21.2,70.9 22.7,69.4 v1(26.1,69.4)
  Bottom Layer w0.2: 10.4,38.934 10.4,42.9 10.9,43.4 10.9,55.8 12.8,57.7 12.8,68.4 v1(14.5,70.1) ; 10.417,38.917 10.8,38.534 10.8,38.5 14.4,34.9 22,34.9 U1.B12@22.5,35.4 ; HDR1.30@26.1,67.3 v1(26.1,69.4)
FPGA_CLK_2: HDR1.32 U1.AB12 | length 91.8
  Top Layer w0.2: v1(52.6,35.1) v1(52.6,41.8)
  MidLayer1 w0.2: v1(26.9,68.8) 26.9,70.5 26.2,71.2 26.2,72.4 26.5,72.7 30.7,72.7 v1(31.5,73.5) ; v1(31.5,76.3) 33.366,76.3 34.566,75.1 46.7,75.1 48.4,73.4 54.1,73.4 55.8,71.7 55.8,60.3 57.5,58.6 57.5,43.3 56,41.8 v1(52.6,41.8)
  Bottom Layer w0.2: HDR1.32@26.9,67.3 v1(26.9,68.8) ; v1(31.5,73.5) v1(31.5,76.3) ; U1.AB12@42.5,35.4 50.3,35.4 50.4,35.5 52.1,35.5 52.5,35.1 v1(52.6,35.1)
FPGA_DIN: HDR1.64 TP14.1 U1.AA14 | length 95.7
  Top Layer w0.2: TP14.1@41.8,73.5 43.8,75.5 v1(43.8,76.6)
  MidLayer1 w0.2: v1(41,33.9) 42,33.9 42.8,33.1 48.9,33.1 49.7,32.3 54.4,32.3 56,30.7 57.3,30.7 57.7,30.3 v1(58.7,30.3) ; v1(43.8,76.6) 44.8,75.6 48.7,75.6 49.413,74.887 55.413,74.887 56.727,73.573 56.727,60.608 58.4,58.934 58.4,41.1 64,35.5 v1(64,32.3)
  Bottom Layer w0.2: HDR1.64@39.7,67.3 39.7,68.5 39.4,68.8 39.4,70.5 39.7,70.8 40.5,71.6 40.5,72.2 TP14.1@41.8,73.5 ; v1(41,33.9) 41.45,33.45 U1.AA14@41.5,33.4 ; v1(58.7,30.3) 59,30.6 62.3,30.6 v1(64,32.3)
FPGA_DONE: R6.2 U1.AB21 | length 106.5
  Top Layer w0.2: R6.2@47.5,67.9 48.3,67.9 48.592,68.192 48.592,68.992 49.5,69.9 v1(49.5,70.7)
  MidLayer1 w0.2: v1(49.5,77.9) 55.8,77.9 67.6,66.1 67.6,40.3 66.3,39 v1(66.3,20.6)
  Bottom Layer w0.2: U1.AB21@42.5,26.4 44.1,24.8 49.534,24.8 53.734,20.6 v1(66.3,20.6) ; v1(49.5,70.7) v1(49.5,77.9)
FPGA_DONE_R: HDR1.74 R4.2 R6.1 U5.2 | length 134
  Top Layer w0.2: U5.2@25.65,4.55 27.2,4.55 27.25,4.5 29,4.5 29.2,4.3 v1(29.2,3.7) ; R4.2@42.8,67.95 R4.2@43,67.95 44.1,67.95 ; v1(44.1,69.1) 44.1,67.95 ; R6.1@45.5,67.95 45.45,67.9 45.3,67.9 45.25,67.95 44.1,67.95 ; v1(55.4,74) 52.6,74 52.1,73.5 52.1,71.4 51.7,71 51.5,71 50.8,70.3 50.8,69.8 50,69 50,67.9 48.2,66.1 45.1,66.1 44.1,67.1 44.1,67.95
  MidLayer1 w0.2: v1(29.2,3.7) 43.235,3.7 43.535,3.4 45.6,3.4 46,3.8 50.2,3.8 50.6,3.4 55,3.4 58.8,7.2 61.3,7.2 64.3,10.2 64.3,22.8 63.4,23.7 63.4,35.5 58,40.9 58,58.7 56.327,60.373 56.327,73.073 v1(55.4,74)
  Bottom Layer w0.2: HDR1.74@43.7,67.3 43.7,68.7 v1(44.1,69.1)
FPGA_INIT: HDR1.68 R3.1 TP13.1 U1.W12 | length 81.7
  Top Layer w0.2: R3.1@40.4,67.95 40.4,68.1 40.7,68.4 40.7,68.932 40.9,69.132 41.132,69.132 TP13.1@42,70 42,71.3 v1(43.6,72.9) ; v1(51.7,34.9) v1(51.7,41.8)
  MidLayer1 w0.127: 38.5,38.4 39.5,38.4
  MidLayer1 w0.2: 38.5,38.4 38.4,38.3 38.4,36.5 v1(39,35.9) ; 39.5,38.4 39.7,38.2 39.7,37.766 40.866,36.6 43.3,36.6 44.381,35.519 51.081,35.519 v1(51.7,34.9) ; v1(43.6,72.9) 47.4,72.9 48.8,71.5 49.6,71.5 50.2,70.9 51.9,70.9 52.3,71.3 54.9,71.3 55.4,70.8 55.4,60.134 57.1,58.434 57.1,43.7 55.8,42.4 52.3,42.4 v1(51.7,41.8)
  Bottom Layer w0.2: v1(39,35.9) 39.45,35.45 U1.W12@39.5,35.4 ; HDR1.68@41.3,67.3 41.3,69.3 TP13.1@42,70
FPGA_M0: R8.2 U1.AB2 | length 30.4
  Top Layer w0.2: R8.2@38.2,73.6 38.2,73.5 38.2,72.7 v1(38.7,72.2)
  MidLayer1 w0.2: v1(38.7,72.2) 38.7,71 38.8,70.9 38.8,62.166 42.1,58.866 42.1,49.2 v1(42.2,49.1)
  Bottom Layer w0.2: v1(42.2,49.1) 43,48.3 43,45.9 U1.AB2@42.5,45.4
FPGA_M0_R: HDR1.60 R8.7 | length 5.4
  Top Layer w0.3: v1(38.1,71.5) 38.135,71.565 38.135,71.5 R8.7@38.135,70.425
  Bottom Layer w0.2: HDR1.60@38.1,67.3 v1(38.1,71.5)
FPGA_M1: R8.3 U1.AA1 | length 29.1
  Top Layer w0.2: R8.3@36.9,73.5 36.9,72.8 v1(37.3,72.4)
  MidLayer1 w0.2: v1(37.3,72.4) 37.3,71.9 37.4,71.8 37.4,71.3 38.4,70.3 38.4,62 41.6,58.8 v1(41.6,48.4)
  Bottom Layer w0.2: U1.AA1@41.5,46.4 41.5,48.4 v1(41.6,48.4)
FPGA_M1_R: HDR1.58 R8.6 | length 5.5
  Top Layer w0.3: R8.6@36.8,70.6 v1(36.8,71.6)
  Bottom Layer w0.2: v1(36.8,71.6) 37.3,71.1 HDR1.58@37.3,67.3
FPGA_M2: R8.4 U1.AB3 | length 32.1
  Top Layer w0.2: v1(35.7,72.4) R8.4@35.7,73.1
  MidLayer1 w0.2: v1(35.7,72.4) 36.2,71.9 36.2,71.4 38,69.6 38,61.834 41,58.834 v1(41,44.9)
  Bottom Layer w0.2: v1(41,44.9) 42,44.9 U1.AB3@42.5,44.4
FPGA_M2_R: HDR1.56 R8.5 | length 5.9
  Top Layer w0.3: R8.5@35.595,70.425 35.595,71.5 35.595,71.595 v1(35.6,71.5)
  Bottom Layer w0.2: v1(35.6,71.5) 36.5,70.7 HDR1.56@36.5,67.3
FPGA_PROGRAM: R8.1 TP4.1 U1.A2 | length 59.9
  Top Layer w0.2: TP4.1@33,71.5 34.7,73.2 34.7,74.3 34.9,74.5 39.3,74.5 39.405,74.395 R8.1@39.405,73.575
  MidLayer1 w0.2: 13.3,68.6 13.369,68.531 ; v1(19,56.8) 19,62.9 13.369,68.531 ; v1(23.1,72.2) 14.3,72.2 12.8,70.7 12.8,69.1 13.369,68.531
  Bottom Layer w0.2: v1(19,56.8) 21,54.8 21,45.9 21.45,45.45 U1.A2@21.5,45.4 ; v1(23.1,72.2) 24.3,72.2 24.7,72.6 27,72.6 27.4,72.2 30.5,72.2 30.9,72.6 31.9,72.6 TP4.1@33,71.5
FPGA_PROGRAM_R: HDR1.62 R1.1 R8.8 | length 10.6
  Top Layer w0.2: v1(39.4,71.6) 40.4,72.6 40.4,74.7 40.05,75.05 R1.1@40.05,76
  Top Layer w0.3: v1(39.4,71.6) 39.4,70.43 R8.8@39.405,70.425
  Bottom Layer w0.2: HDR1.62@38.9,67.3 38.9,71.1 v1(39.4,71.6)
FPGA_TCK: R9.3 TP11.1 U1.A21 | length 107.5
  Top Layer w0.2: TP11.1@22.5,74 24.3,75.8 29.6,75.8 30.8,77 33.4,77 34.2,77.8 44.3,77.8 45.3,76.8 45.3,75.1 45.865,74.535 R9.3@45.865,73.575
  MidLayer2 w0.2: v1(18,25.4) 19.5,25.4 19.7,25.6 v1(20.7,25.6)
  Bottom Layer w0.2: v1(18,25.4) 15.3,28.1 10.8,28.1 7.9,31 3.1,31 1.6,32.5 1.6,63 11.9,73.3 21.8,73.3 TP11.1@22.5,74 ; v1(20.7,25.6) U1.A21@21.5,26.4
FPGA_TCK_R: HDR1.72 R9.6 | length 6.6
  Top Layer w0.3: v1(45.5,71.6) 45.9,70.46 R9.6@45.865,70.425
  Bottom Layer w0.2: HDR1.72@42.9,67.3 42.9,68.8 43.517,69.417 43.517,69.617 v1(45.5,71.6)
FPGA_TDI: R9.1 TP9.1 U1.B1 | length 72.5
  Top Layer w0.2: R9.1@48.405,73.575 49.425,73.575 TP9.1@51,72
  MidLayer1 w0.2: v1(19.7,57.5) 19.7,62.8 13.2,69.3 13.2,70.5 14.5,71.8 21.9,71.8 22.1,71.6 24,71.6 27.7,75.3 33.8,75.3 34.4,74.7 46.3,74.7 49,72 TP9.1@51,72
  Bottom Layer w0.2: v1(19.7,57.5) 21.7,55.5 21.7,49.2 22.5,48.4 U1.B1@22.5,46.4
FPGA_TDI_R: HDR1.78 R9.8 | length 7.2
  Top Layer w0.3: v1(47.5,71.6) 48.2,71.6 48.4,71.4 48.4,70.43 R9.8@48.405,70.425
  Bottom Layer w0.2: HDR1.78@45.3,67.3 45.3,68.5 45.8,69 45.8,69.9 v1(47.5,71.6)
FPGA_TDO: R9.2 TP10.1 U1.B22 | length 119.6
  Top Layer w0.2: v1(29.5,78.6) 32.4,78.6 32.9,79.1 34.7,79.1 35,78.8 44.7,78.8 44.882,78.618 45.9,77.6 46.8,77.6 47.5,76.9 47.5,75 47.135,74.635 R9.2@47.135,73.575
  MidLayer2 w0.2: v1(18,23.9) 21.7,23.9 v1(22.4,24.6)
  Bottom Layer w0.2: v1(18,23.9) 14.2,27.7 10.4,27.7 7.5,30.6 2.8,30.6 1.2,32.2 1.2,63.3 11.6,73.7 19.5,73.7 21,75.2 25.4,75.2 27.9,72.7 28.7,72.7 TP10.1@30,74 30,76.6 29.5,77.1 v1(29.5,78.6) ; v1(22.4,24.6) 22.5,24.8 U1.B22@22.5,25.4
FPGA_TDO_R: HDR1.54 R2.1 R9.7 | length 19.3
  Top Layer w0.2: v1(35.8,69) 36.9,69 37.95,67.95 R2.1@38,67.95 38.95,67 41.5,67 41.7,67.2 41.7,68.6 42,68.9 42.6,68.9 43.5,69.8 43.5,71.8 44.1,72.4 45.7,72.4 47.135,70.965 R9.7@47.135,70.425
  Bottom Layer w0.2: HDR1.54@35.7,67.3 35.7,68.9 v1(35.8,69)
FPGA_TMS: R9.4 TP12.1 U1.A20 | length 101
  Top Layer w0.2: TP12.1@24.8,74 26.6,74 27.8,75.2 31.5,75.2 32.9,76.6 33.7,76.6 34.4,77.3 44.09,77.3 44.595,76.795 R9.4@44.595,73.575
  MidLayer2 w0.2: v1(18,27.2) v1(20.7,27.2)
  Bottom Layer w0.2: v1(18,27.2) 16.7,28.5 11.2,28.5 6.6,33.1 6.6,34.5 2,39.1 2,62.7 12.1,72.8 23.6,72.8 TP12.1@24.8,74 ; v1(20.7,27.2) 21.1,27.4 U1.A20@21.5,27.4
FPGA_TMS_R: HDR1.70 R9.5 | length 6.6
  Top Layer w0.3: R9.5@44.595,70.425 44.6,70.43 v1(44.6,71.6)
  Bottom Layer w0.2: HDR1.70@42.1,67.3 42.1,68.566 43.117,69.583 43.117,70.2 44.517,71.6 v1(44.6,71.6)
GND: C1.2 C2.2 C3.2 C4.2 C5.2 C6.2 C7.2 C8.2 C9.2 C10.2 C11.2 C12.2 C13.2 C14.2 C15.2 C16.2 C17.2 C18.1 C19.2 C20.2 C21.2 C22.2 C23.2 C24.2 C25.2 C26.2 C27.2 C28.2 C29.2 C30.2 C31.2 C32.2 C33.2 C34.2 C35.2 C36.2 C37.2 C38.2 C39.2 C40.2 C41.2 C42.2 C43.2 C44.2 C45.2 C46.2 C47.2 C48.2 C49.2 C50.2 C51.2 C52.2 C53.2 C54.2 C55.2 C56.2 C57.2 C58.2 C59.2 C60.2 C61.2 C62.2 C63.2 C64.2 C65.2 HDR1.1 HDR1.36 HDR1.38 HDR1.40 HDR1.42 HDR1.98 HDR1.100 HDR2.1 HDR2.98 HDR2.100 LED1.2 R11.2 R15.2 U1.A1 U1.A22 U1.AA2 U1.AA21 U1.AB1 U1.AB22 U1.B2 U1.B21 U1.C9 U1.C14 U1.J3 U1.J9 U1.J10 U1.J11 U1.J12 U1.J13 U1.J14 U1.J20 U1.K9 U1.K10 U1.K11 U1.K12 U1.K13 U1.K14 U1.L9 U1.L10 U1.L11 U1.L12 U1.L13 U1.L14 U1.M9 U1.M10 U1.M11 U1.M12 U1.M13 U1.M14 U1.N9 U1.N10 U1.N11 U1.N12 U1.N13 U1.N14 U1.P3 U1.P9 U1.P10 U1.P11 U1.P12 U1.P13 U1.P14 U1.P20 U1.Y9 U1.Y14 U3.12 U3.34 U4.12 U4.34 U5.3 | length 232
  Top Layer w0.2: C20.2@26.5,50.3 v1(26.5,51.3) ; C50.2@28.5,51.2 C50.2@28.5,51.25 v1(28.5,52.3)
  Top Layer w0.3: C27.2@19.5,24.15 21.15,24.15 v1(21.5,24.5) ; C8.2@20.15,43.5 20.6,43.95 v1(20.6,44.6) ; C54.2@22.85,37.5 22.85,37.75 v1(24,38.9) ; C10.2@22.95,32.9 23.95,33.9 v1(24,33.9) ; U5.3@25.7,5.5 v1(26.9,5.5) ; v1(27,42.9) 27.25,42.75 C28.2@28,42.75 ; C48.2@28,5.4 v1(29,5.4) ; v1(28,27.9) C18.1@29,27.9 ; C57.2@28,29.55 28,29.5 28.6,28.9 v1(30,28.9) ; C38.2@28.25,70.498 28.802,70.498 v1(29.3,70) ; v1(28.5,47.5) 29,47 C15.2@29,45.85 ; C33.2@28.85,38.9 C33.2@29,38.9 ; v1(29,33.9) 28.35,33.25 C29.2@28.35,32.9 C34.2@30,32.9 ; v1(29,35.9) 29,36.9 v1(29,37.9) C33.2@29,38.9 ; C33.2@29,39 C33.2@29,38.9 ; C56.2@29.85,34.9 v1(31,34.9) ; C34.2@30,32.75 C34.2@30,32.9 ; v1(30,33.9) C34.2@30,32.9 ; v1(30,39) 29.8,38.9 C33.2@29,38.9 ; C40.2@30,42.75 v1(30,43.9) ; v1(31,33.9) v1(31,32.9) ; C14.2@32,32.75 C14.2@32,32.9 ; v1(32,33.9) C14.2@32,32.9 ; v1(32,37.9) C42.2@32,39.05 ; v1(33,33.9) v1(33,32.9) ; v1(33,34.9) C44.2@34,34.9 ; v1(34,26.9) 34,26.2 34.05,26.15 C49.2@35,26.15 ; C16.2@34,32.75 C16.2@34,32.9 ; v1(34,33.9) C16.2@34,32.9 ; C41.2@34,39.05 v1(34,37.9) 34,36.9 v1(34,35.9) C44.2@34,34.9 ; C9.2@34,45.15 v1(34,43.9) 34,43.4 34.65,42.75 C7.2@36,42.75 ; C44.2@34.15,34.9 C44.2@34,34.9 ; v1(35,33.9) 35.65,33.25 C31.2@35.65,32.9 C16.2@34,32.9 ; v1(35,37.9) 35.65,38.55 C30.2@35.65,38.9 ; C11.2@36,46.2 v1(36,47.5) ; C21.2@37.6,49.95 v1(37.6,51) ; C53.2@40.75,31.9 41,32.15 v1(41,32.9) ; v1(41,37.9) C52.2@41.9,37.9 ; v1(43.9,21.6) 44.5,22.2 C26.2@44.5,22.65 ; R15.2@45.35,43.5 45.35,43.85 v1(46.3,44.8) ; v1(45.5,48.6) 45.5,47.8 C60.2@46,47.2 ; C60.2@46,47 C60.2@46,47.2 ; C36.2@46.35,3 v1(47.5,3) ; C24.2@46.45,41.2 47.1,41.2 v1(47.6,41.8) ; R11.2@47,62.95 47,64 47.9,64.9 49.7,64.9 53.8,69 v3(53.8,69.2) v3(53.8,70) ; v1(47.5,47.2) C60.2@46,47.2 ; LED1.2@50.45,5.5 LED1.2@50.45,5.3 ; v1(52,5.5) 50.5,5.5 50.497,5.488 LED1.2@50.45,5.3 ; C34.2@30,32.9 v1(31,32.9) ; v1(31,32.9) C14.2@32,32.9 ; C14.2@32,32.9 v1(33,32.9) ; v1(33,32.9) C16.2@34,32.9 ; LED1.2@50.45,5.3 50.45,5.15 50.4,5.1 LED1.2@50.45,5.3
  Top Layer w0.4: v1(5.2,47.9) 5.65,48.35 C35.2@6.5,48.35 ; C64.2@9.3,49 v1(9.3,50.6) ; C12.2@12.2,46.65 12.65,46.65 13.1,47.1 v1(13.8,47.1) ; v1(16.7,30.5) 17.675,29.525 C22.2@17.8,29.4 ; v1(18,23) 18.5,22.5 C55.2@19.15,22.5 ; C23.2@18.2,41.5 v1(18.2,42.4) ; v1(18.7,40.1) 18.9,39.9 C51.2@23.15,39.9 ; v1@21.9,47.05 C32.2@21.9,48 ; v1(26.5,20.4) C19.2@26.5,21.55 ; v1(34,28.9) 35.4,28.9 C25.2@36,29.5 ; C6.2@40.45,23.9 v1(41.5,23.9) ; v1(45.5,49.3) 45.5,51 v1(45.5,52.8) ; v1(45.5,54) C17.2@46.65,54 ; C5.2@46.35,30.5 v1(47.4,30.5) ; C13.2@51.5,30.9 v1(52.8,30.9) ; C37.2@53.85,16.5 55,16.5 v3(55.3,16.2) ; v1(64.2,29.8) 65.35,29.8 C47.2@65.5,29.65
  Top Layer w0.5: C3.2@4.2,27.5 C3.2@4.3,27.5 v3(6.4,27.5) ; v3(6,57.7) C39.2@7.3,57.7 ; v3(8,21.4) C1.2@10.2,21.4 ; v3(13.8,58.7) 14,58.5 C61.2@14,57 ; v3(21.7,19.9) C58.2@23.5,19.9 ; C62.2@32,19.7 32.3,19.7 32.7,19.9 v1(32.7,21.2) ; C59.2@53,65.5 53,67 54.6,68.6 v3(54.6,69.2) ; C46.2@57.7,31.4 C46.2@57.7,31.35 57.7,31.2 v1(58.7,31.2) ; v3(58,71.8) 59.4,71.8 C2.2@60.2,72 ; C63.2@60.8,28.1 v1(60.8,29.5) ; C4.2@66,67.2 v3(66,69.2)
  Bottom Layer w0.2: HDR2.1@14.9,9.7 HDR2.1@14.9,10.1 ; v1(21.5,24.5) U1.A22@21.5,25.4 ; U1.A1@21.5,46.4 v1(21.9,47) ; v1(22,25.9) U1.B21@22.5,26.4 ; v1(22,45.9) U1.B2@22.5,45.4 ; U1.C14@23.5,33.4 v1(24,33.9) ; U1.C9@23.5,38.4 v1(24,38.9) ; HDR1.36@28.5,67.3 28.5,68.5 29,69 30.9,69 ; v1(29,33.9) U1.J13@29.5,34.4 ; v1(29,35.9) 29.45,35.45 U1.J12@29.5,35.4 ; v1(29,37.9) 29.45,37.45 U1.J10@29.5,37.4 ; 29.3,69 v1(29.3,70) ; U1.J20@29.5,27.4 30,27.9 v1(30,28.9) ; U1.J14@29.5,33.4 29.55,33.45 v1(30,33.9) ; U1.J11@29.5,36.4 29.55,36.45 v1(30,36.9) ; U1.J9@29.5,38.4 v1(30,37.9) ; U1.J3@29.5,44.4 v1(30,43.9) ; v1(30,35.9) 30.45,35.45 U1.K12@30.5,35.4 ; HDR1.40@30.1,67.3 30.1,69 ; U1.K14@30.5,33.4 v1(31,33.9) U1.L13@31.5,34.4 ; U1.K13@30.5,34.4 30.55,34.45 v1(31,34.9) U1.L12@31.5,35.4 ; U1.K11@30.5,36.4 v1(31,35.9) ; U1.K10@30.5,37.4 v1(31,37.9) ; U1.K9@30.5,38.4 30.55,38.45 v1(31,38.9) ; HDR1.42@30.9,67.2 v1(30.9,69.9) v1@30.9,69.8 ; v1(31,32.9) U1.L14@31.5,33.4 ; v1(31,36.9) U1.L10@31.5,37.4 ; U1.L11@31.5,36.4 v1(32,35.9) ; U1.L9@31.5,38.4 v1(32,37.9) ; v1(32,33.9) 32.45,33.45 U1.M14@32.5,33.4 ; v1(32,34.9) U1.M12@32.5,35.4 ; v1(32,36.9) U1.M10@32.5,37.4 ; U1.M13@32.5,34.4 v1(33,34.9) ; U1.M11@32.5,36.4 v1(33,35.9) ; U1.M9@32.5,38.4 32.55,38.45 v1(33,38.9) ; v1(33,32.9) U1.N14@33.5,33.4 ; v1(33,33.9) U1.N13@33.5,34.4 ; v1(33,37.9) U1.N9@33.5,38.4 ; U1.N12@33.5,35.4 33.55,35.45 v1(34,35.9) ; U1.N11@33.5,36.4 v1(33,36.9) U1.N10@33.5,37.4 ; v1(34,26.9) U1.P20@34.5,27.4 ; v1(34,33.9) U1.P13@34.5,34.4 ; v1(34,37.9) U1.P9@34.5,38.4 ; v1(34,43.9) U1.P3@34.5,44.4 ; U1.P14@34.5,33.4 34.55,33.45 v1(35,33.9) ; U1.P12@34.5,35.4 34.55,35.45 v1(35,35.9) U1.P11@34.5,36.4 ; U1.P10@34.5,37.4 34.55,37.45 v1(35,37.9) ; U1.Y14@40.5,33.4 v1(41,32.9) ; U1.Y9@40.5,38.4 v1(41,37.9) ; U1.AA21@41.5,26.4 v1(42,25.9) ; U1.AA2@41.5,45.4 41.55,45.45 v1(42,45.9) ; v1(42.1,47.2) 42.5,46.8 U1.AB1@42.5,46.4 ; U1.AB22@42.5,25.4 v1(43,24.9)
  Bottom Layer w0.3: v1(14,9.3) HDR2.1@14.9,9.3 ; v1(14,10.3) 14.7,10.3 HDR2.1@14.9,10.1
  Bottom Layer w0.4: U4.12@3.925,47.9 v1(5.2,47.9) ; v1(13.8,47.1) U4.34@15.075,47.1 ; v3(13.8,59.9) HDR1.1@14.9,59.9 ; v3(13.8,61) HDR1.1@14.9,61 ; HDR1.38@29.3,67.3 29.3,69.8 v1(29.3,70) ; HDR1.42@30.9,67.3 30.9,69.8 v1(30.9,69.9) ; v1(52.8,30.9) 54.3,30.9 U3.12@54.35,30.9 55.225,30.9 ; 55.3,30.9 58.3,30.9 v1(58.7,31.2) ; v1(64.2,29.8) 64.4,29.8 64.7,30.1 U3.34@65.5,30.1 66.4,30.1 66.5,30 v1(66.9,30)
  Bottom Layer w0.5: v3(13.8,61) v3(13.8,59.9) v3(13.8,58.7) v3(14.9,58.7) 14.9,59.9 HDR1.1@14.9,60.5 ; v3(14.9,8.1) 14.9,9.3 HDR2.1@14.9,9.7 ; HDR2.98@53.3,16.5 53.3,17.6 ; HDR1.98@53.3,67.3 53.3,68.15 53.8,68.65 v3(53.8,69.2) v3(53.8,70) ; HDR2.100@54.1,17.2 54.1,17.1 HDR2.100@54.1,17 ; HDR1.100@54.1,67.3 54.1,68.1 54.6,68.6 v3(54.6,69.2) v3(54.6,70) ; 53.3,17.6 v3@53.8,18.1 ; 53.3,17.6 v3@53.8,18.1 ; v3@53.8,18.1 v3@53.8,18.4 ; v3@53.8,18.1 54.1,18.1 54.697,18.1 54.848,17.948 ; v3@53.8,18.1 v3(54.1,18.4) ; v3@53.8,18.4 53.8,18.7 54.1,18.7 55.3,18.7 55.6,18.7 55.6,18.4 55.6,17.3 55.6,16.2 55.6,16 55.55,15.95 55.5,15.9 55.3,15.9 54.9,15.9 v3@54.9,16.2 ; v3@53.8,18.4 v3(54.1,18.4) ; HDR2.100@54.1,17 HDR2.100@54.1,16.5 54.1,16.2 v3@54.9,16.2 ; HDR2.100@54.1,17 54.9,17 ; v3(54.1,18.4) v3(55.3,18.4) ; 54.848,17.948 54.9,17.897 54.9,17.3 54.9,17 ; 54.848,17.948 v3(55.3,18.4) ; v3@54.9,16.2 v3(55.3,16.2) v3(55.3,17.3) v3(55.3,18.4) ; v3@54.9,16.2 54.9,17
  other v1: 40,69.2
  other v6: 4,70.2
GREEN0: HDR1.10 U1.D4 | length 31.2
  MidLayer1 w0.127: 25.5,44.4 25.5,45.4
  MidLayer1 w0.2: v1(18.1,69.2) 25.5,61.8 25.5,45.4 ; v1(25,43.9) 25.5,44.4
  Bottom Layer w0.2: HDR1.10@18.1,67.3 v1(18.1,69.2) ; U1.D4@24.5,43.4 v1(25,43.9)
GREEN1: HDR1.12 U1.E3 | length 31.6
  MidLayer1 w0.2: v1(18.9,70.1) 18.9,69.1 25.9,62.1 25.9,46.7 26,46.6 v1(26,44.9)
  Bottom Layer w0.2: HDR1.12@18.9,67.3 v1(18.9,70.1) ; U1.E3@25.5,44.4 v1(26,44.9)
HDRIVE: HDR1.18 U1.F5 | length 33.6
  MidLayer1 w0.127: 26.5,43.4 27.4,43.4 27.5,43.5 ; 27.5,44 27.5,43.5 ; 27.5,44.4 27.5,43.5
  MidLayer1 w0.2: v1(21.3,69.2) 27.9,62.6 27.9,44.8 27.5,44.4 ; v1(26,42.9) 26.5,43.4
  Bottom Layer w0.2: HDR1.18@21.3,67.3 v1(21.3,69.2) ; v1(26,42.9) U1.F5@26.5,42.4 ; U1.F5@26.5,42.4 26.55,42.45 U1.F5@26.5,42.4
IO0: HDR2.7 U1.E15 | length 34.4
  MidLayer1 w0.127: 24.5,31.5 24.5,32.4
  MidLayer1 w0.2: v1(17.3,7.3) 17.3,28.4 20.3,31.4 21.1,31.4 21.2,31.3 23.9,31.3 24.3,31.3 24.5,31.5 ; 24.5,32.4 v1(25,32.9)
  Bottom Layer w0.2: v1(17.3,7.3) HDR2.7@17.3,9.7 ; v1(25,32.9) 25.45,32.45 U1.E15@25.5,32.4
IO1: HDR2.9 U1.E16 | length 30.6
  MidLayer1 w0.2: v1(18.1,8.1) 18.1,21.4 18.8,22.1 18.8,27.8 21.9,30.9 24.7,30.9 25,31.2 v1(25,31.9)
  Bottom Layer w0.2: v1(18.1,8.1) HDR2.9@18.1,9.7 ; v1(25,31.9) U1.E16@25.5,31.4
IO2: HDR2.11 U1.F16 | length 32.3
  MidLayer1 w0.2: v1(18.9,7.3) 18.9,21.5 19.2,21.8 19.2,27.6 21.9,30.3 24.4,30.3 24.5,30.4 24.8,30.4 25.4,31 25.4,31.3 v1(26,31.9)
  Bottom Layer w0.2: v1(18.9,7.3) HDR2.11@18.9,9.7 ; v1(26,31.9) U1.F16@26.5,31.4
IO3: HDR2.13 U1.D17 | length 28.1
  MidLayer1 w0.2: v1(19.7,8.1) 19.7,24.3 19.6,24.4 19.6,27.4 22.1,29.9 v1(25,29.9)
  Bottom Layer w0.2: v1(19.7,8.1) HDR2.13@19.7,9.7 ; U1.D17@24.5,30.4 v1(25,29.9)
IO4: HDR2.15 U1.F17 | length 31.5
  MidLayer1 w0.127: 24.5,29.4 25.5,29.4
  MidLayer1 w0.2: v1(20.5,7.3) 20.5,24.4 20,24.9 20,25.8 20.7,26.5 20.9,26.5 21.6,27.2 21.6,28.8 22.2,29.4 22.3,29.5 24.4,29.5 24.5,29.4 ; 25.5,29.4 v1(26,28.9)
  Bottom Layer w0.2: v1(20.5,7.3) HDR2.15@20.5,9.7 ; v1(26,28.9) 26,29.9 U1.F17@26.5,30.4
IO5: HDR2.17 U1.C18 | length 24.6
  MidLayer1 w0.2: v1(21.3,8.1) 21.3,18.8 20.9,19.2 20.9,24.8 21.4,25.3 21.4,26.1 22,26.7 22,28.6 22.3,28.9 v1(23,28.9)
  Bottom Layer w0.2: v1(21.3,8.1) HDR2.17@21.3,9.7 ; v1(23,28.9) U1.C18@23.5,29.4
IO6: HDR2.19 U1.D18 | length 26.7
  MidLayer1 w0.127: 22.5,28.4 23.5,28.4
  MidLayer1 w0.2: v1(22.1,7.3) 22.1,19.1 23.1,20.1 23.1,26.5 22.4,27.2 22.4,28.3 22.5,28.4 ; 23.5,28.4 v1(24,28.9)
  Bottom Layer w0.2: v1(22.1,7.3) HDR2.19@22.1,9.7 ; v1(24,28.9) U1.D18@24.5,29.4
